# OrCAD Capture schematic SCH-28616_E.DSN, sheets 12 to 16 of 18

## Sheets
12 M-02 HDMI: size C
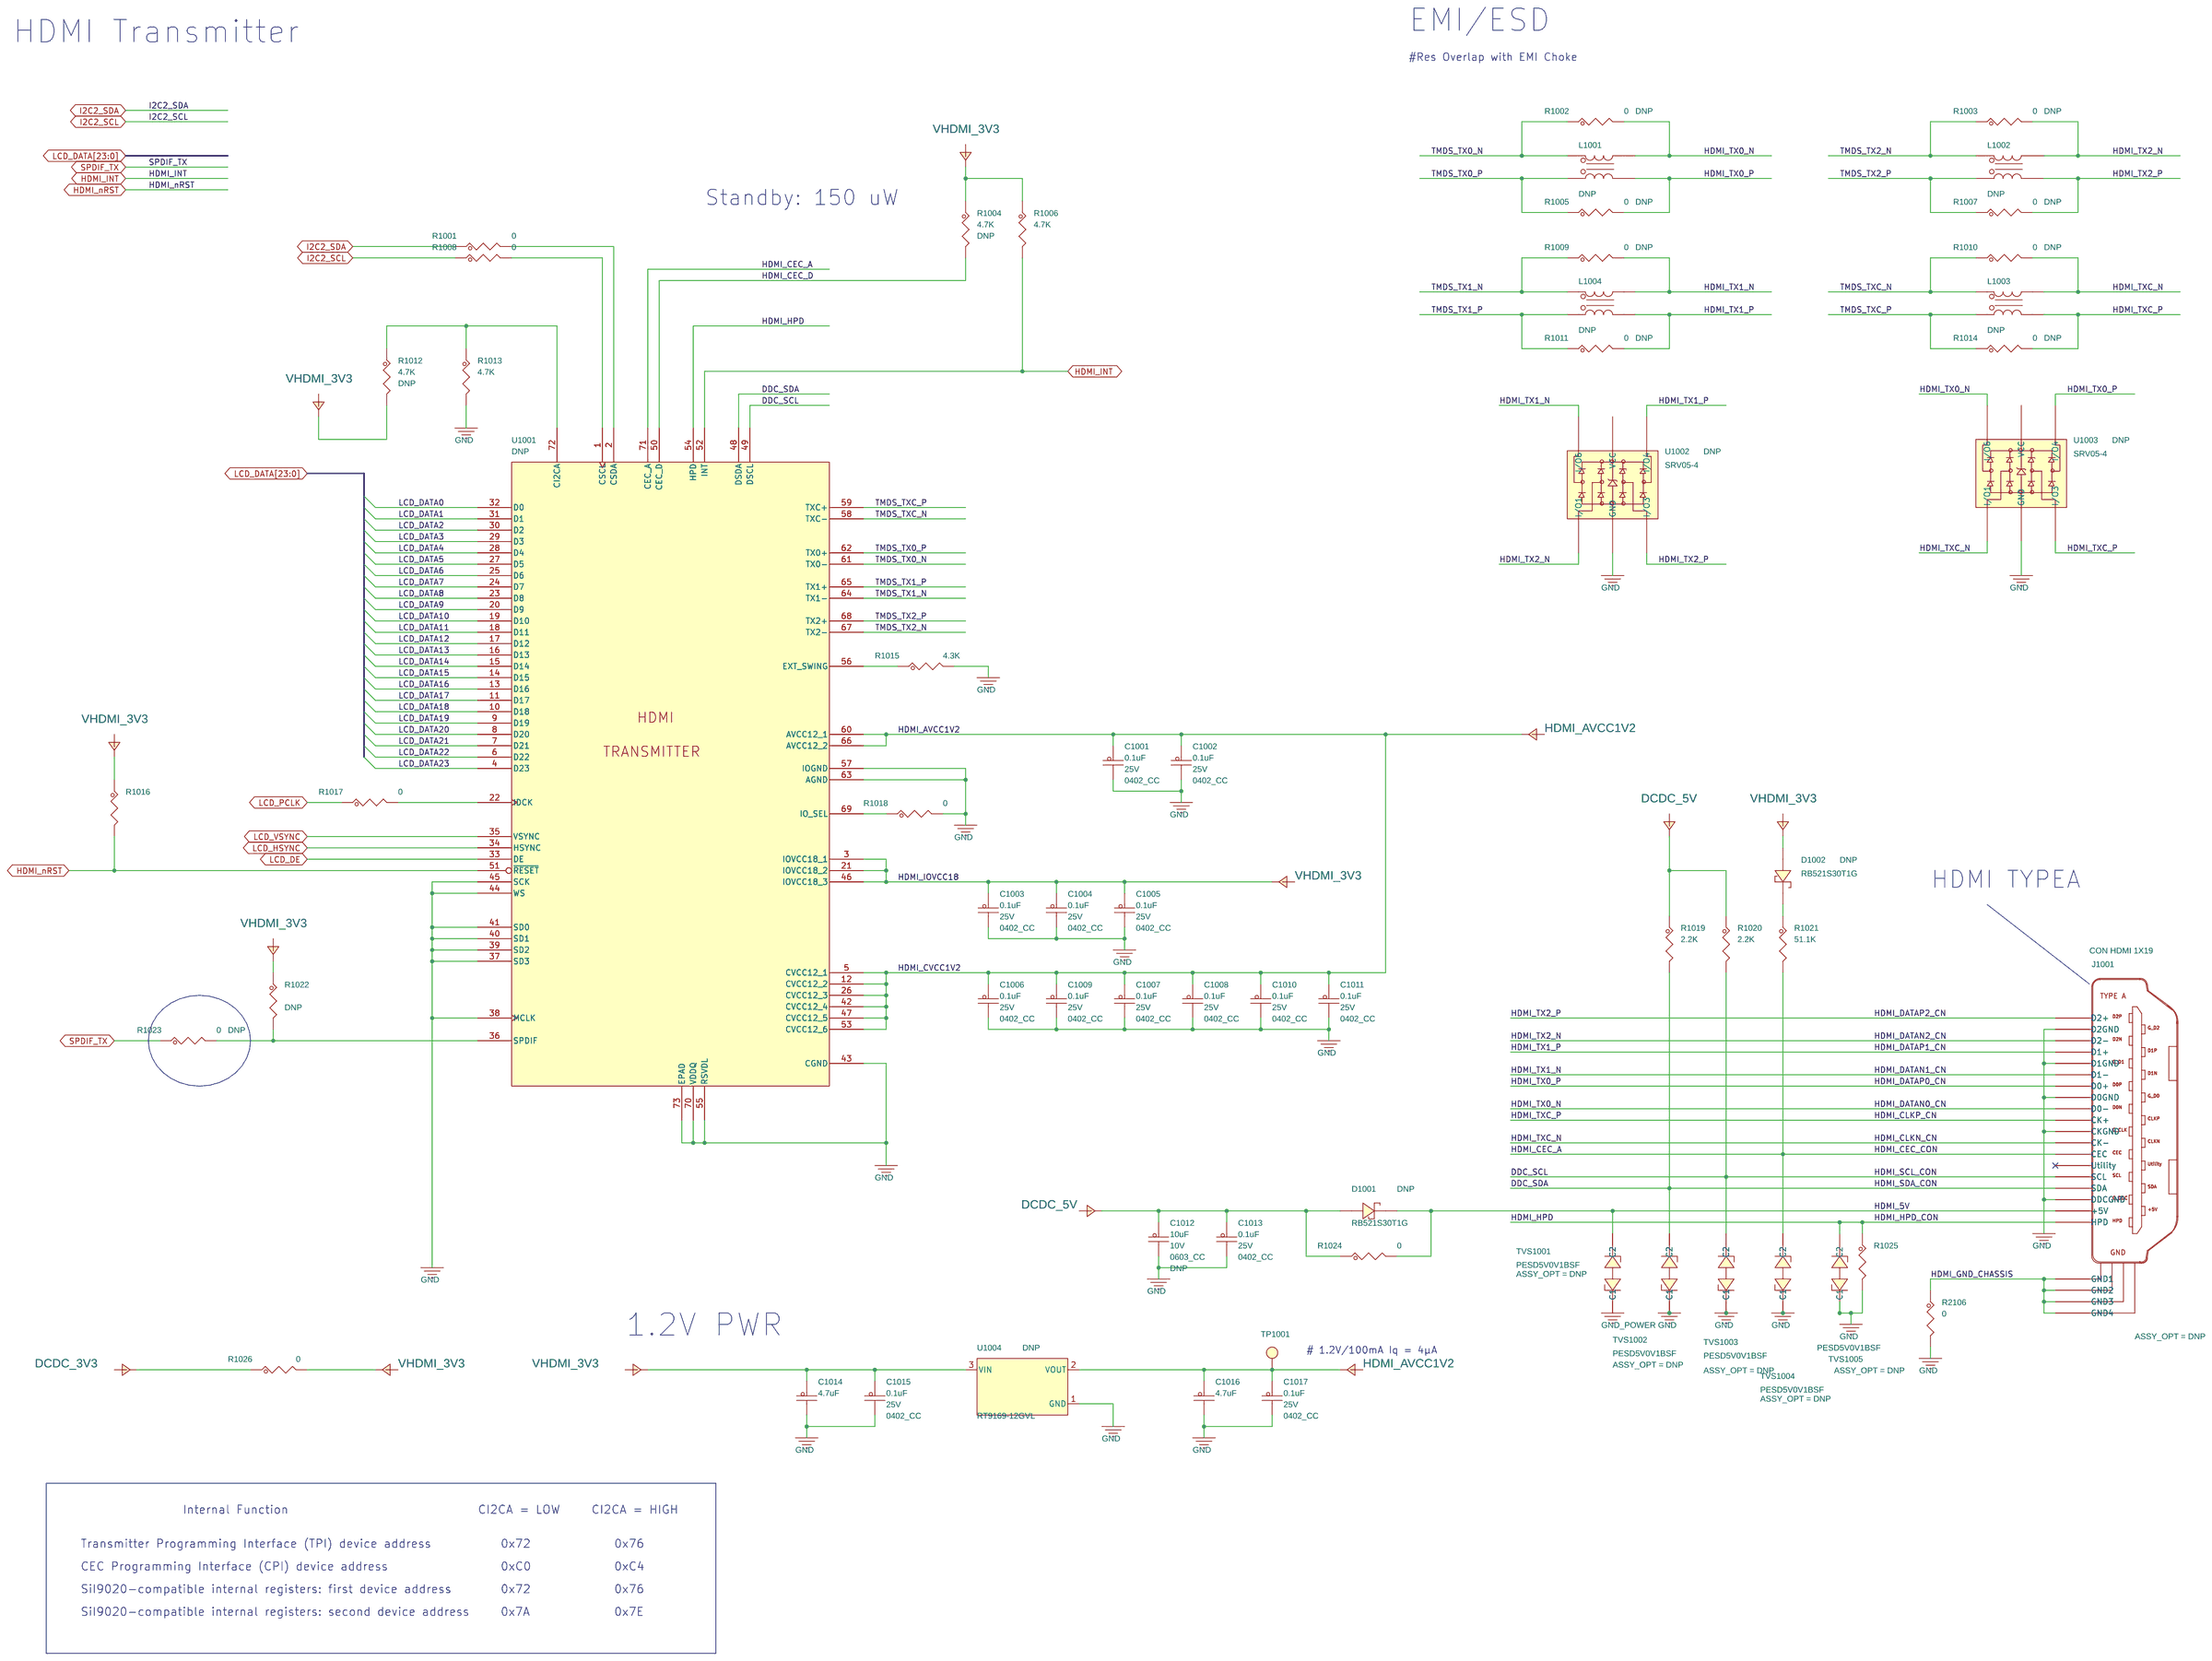
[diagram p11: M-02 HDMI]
13 M-07 Ethernet RMII x1: size C
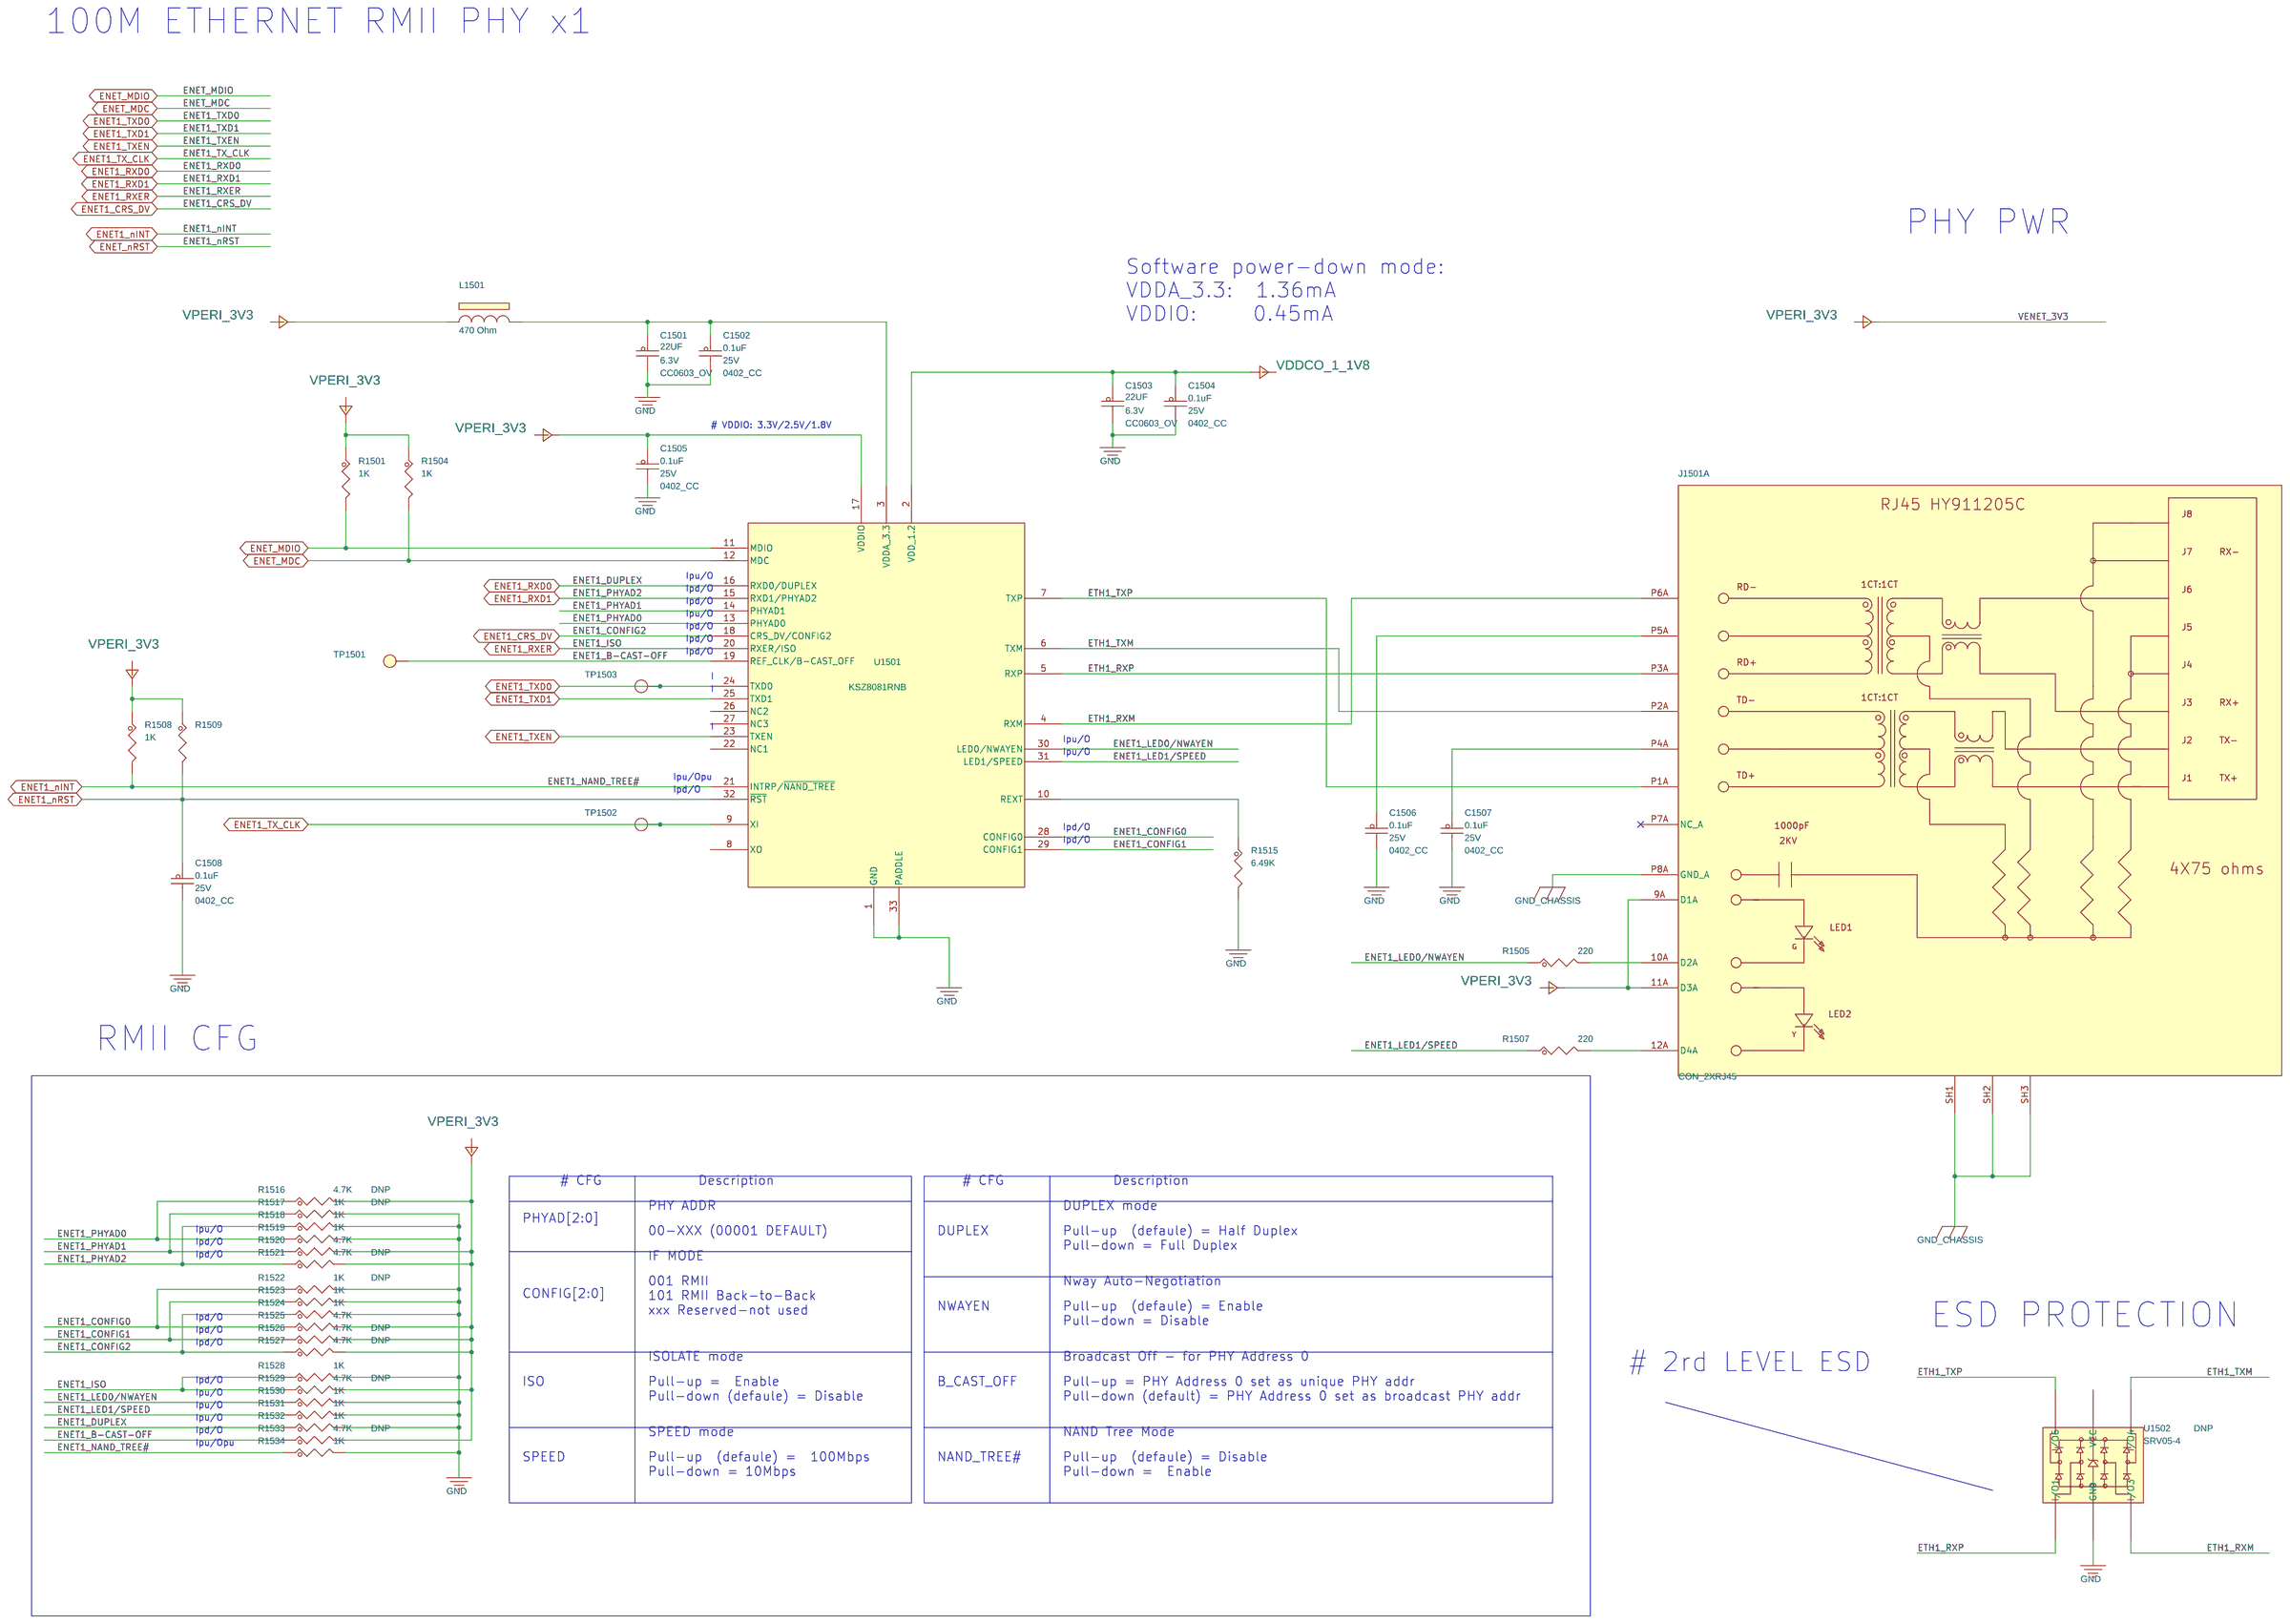
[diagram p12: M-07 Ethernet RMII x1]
14 M-08 Ethernet RMII x2: size C
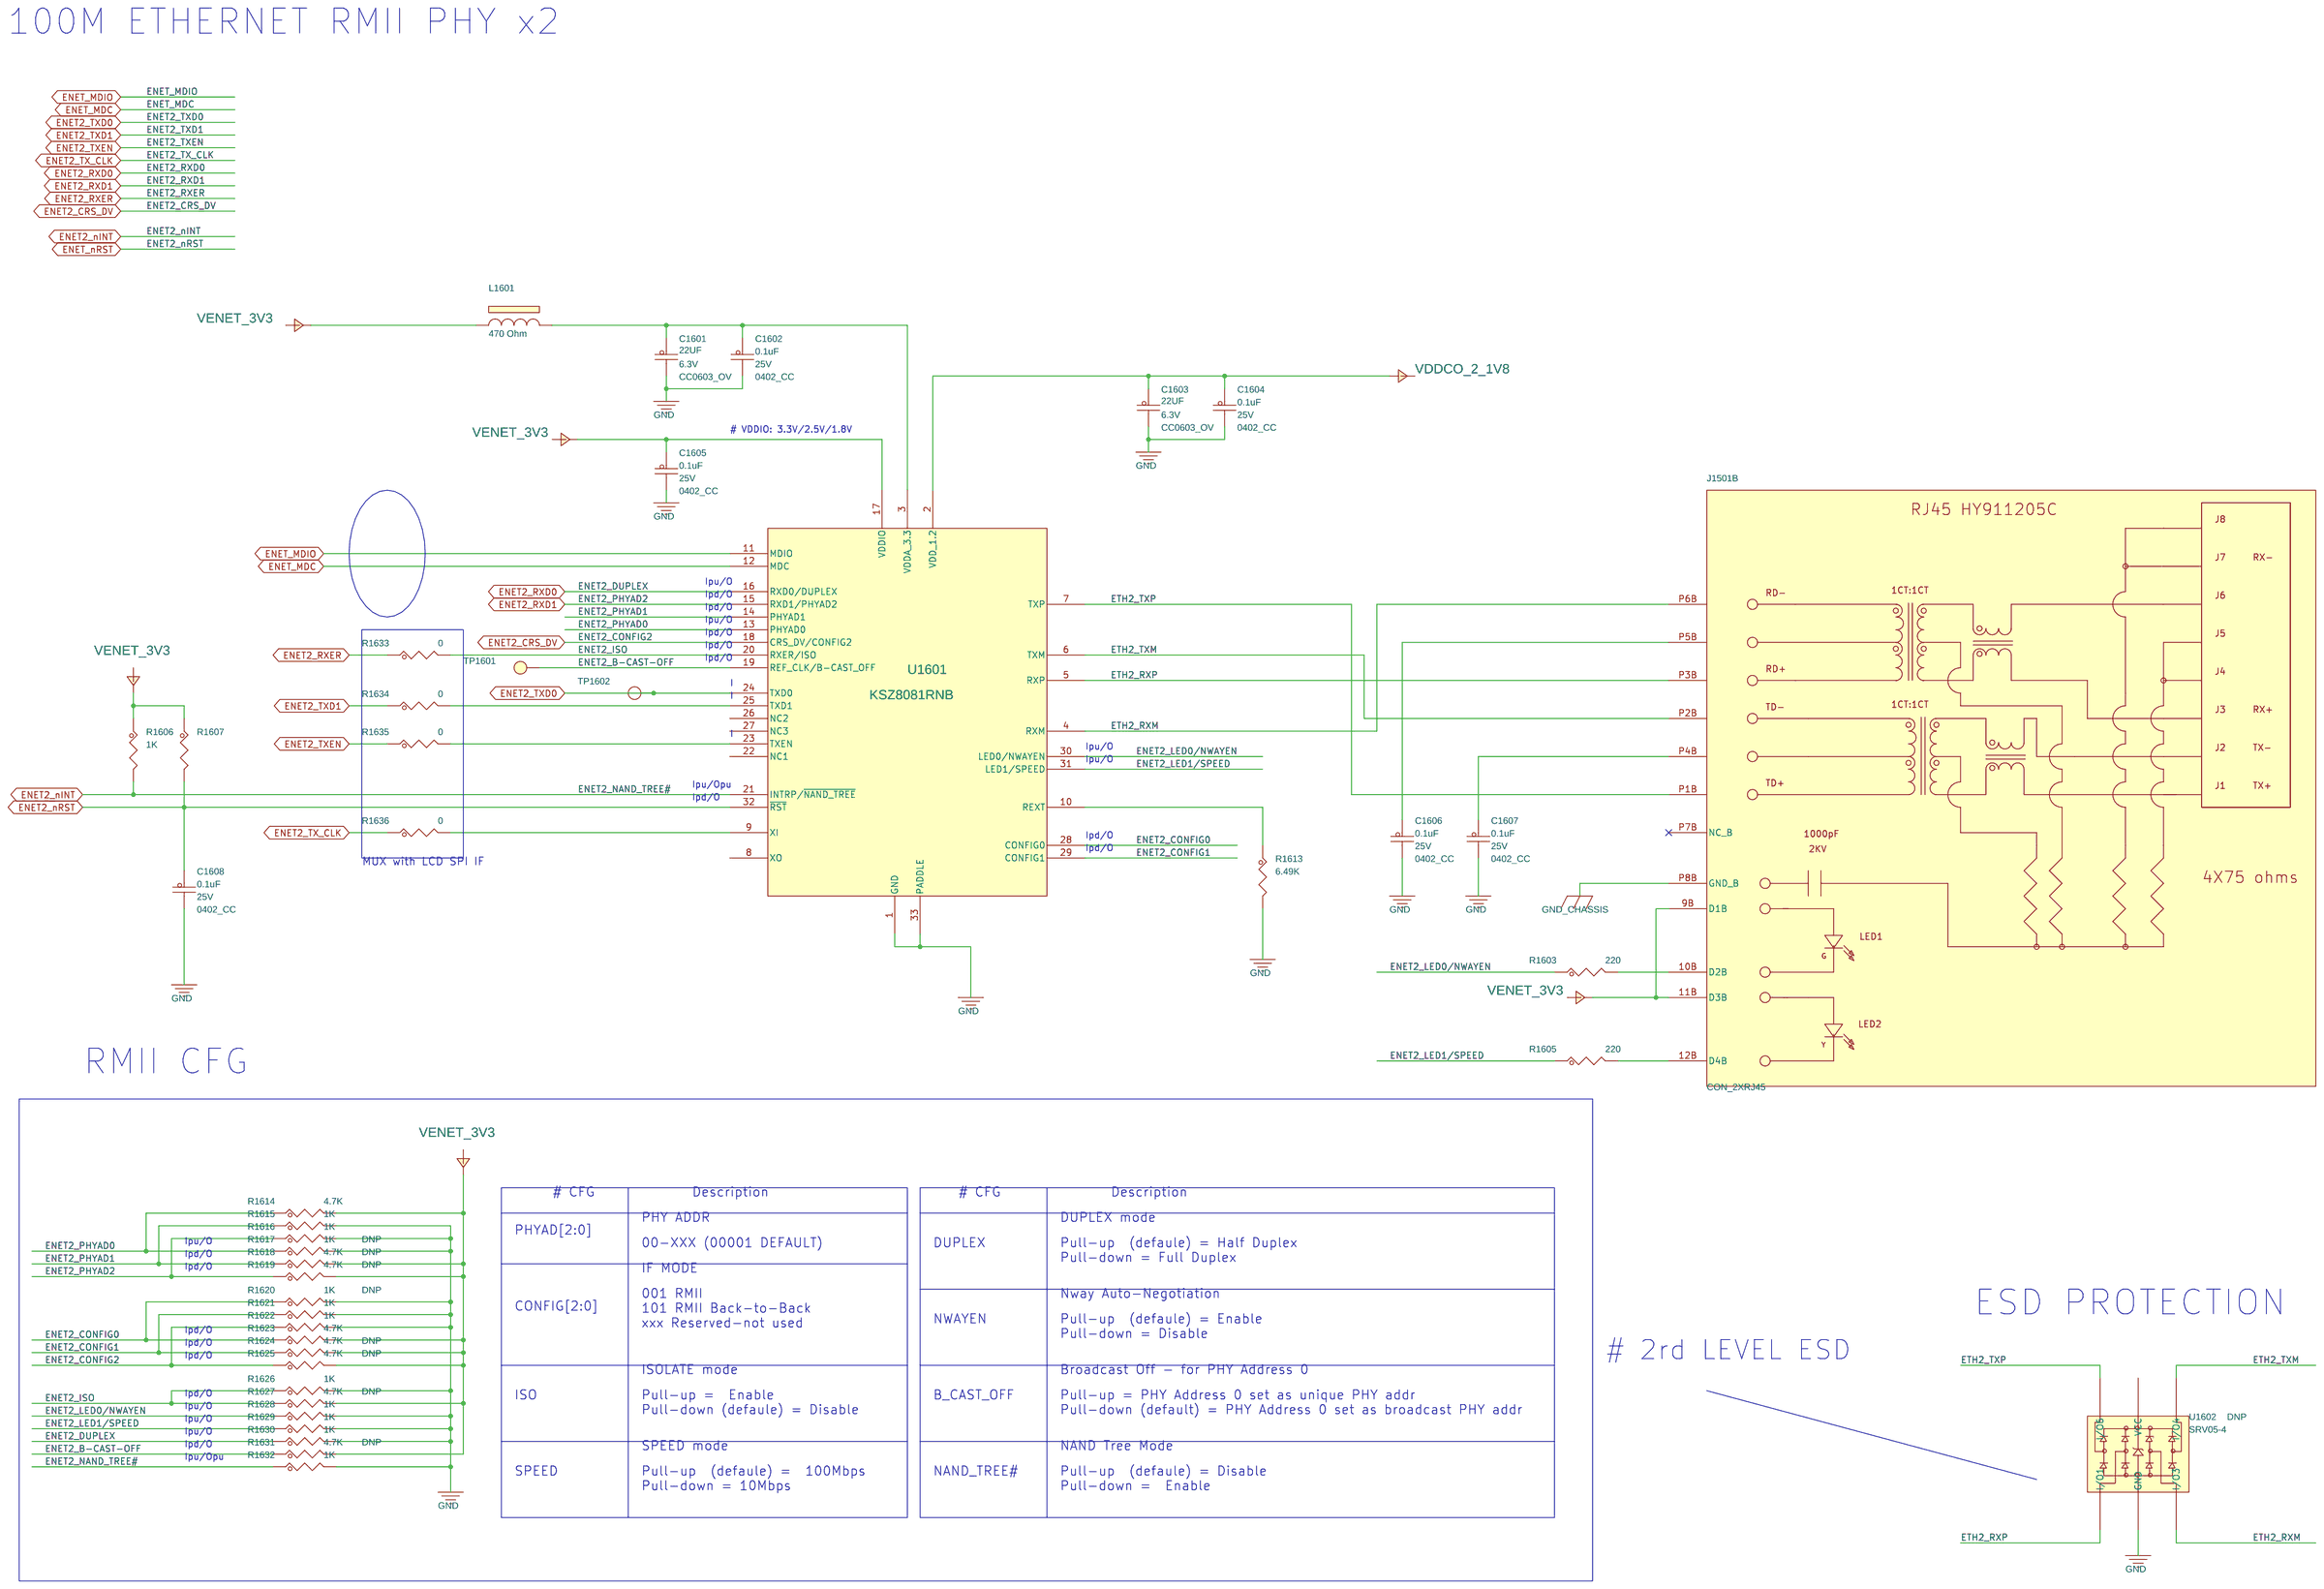
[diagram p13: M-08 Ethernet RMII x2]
15 M-13 SYS POWER: size C
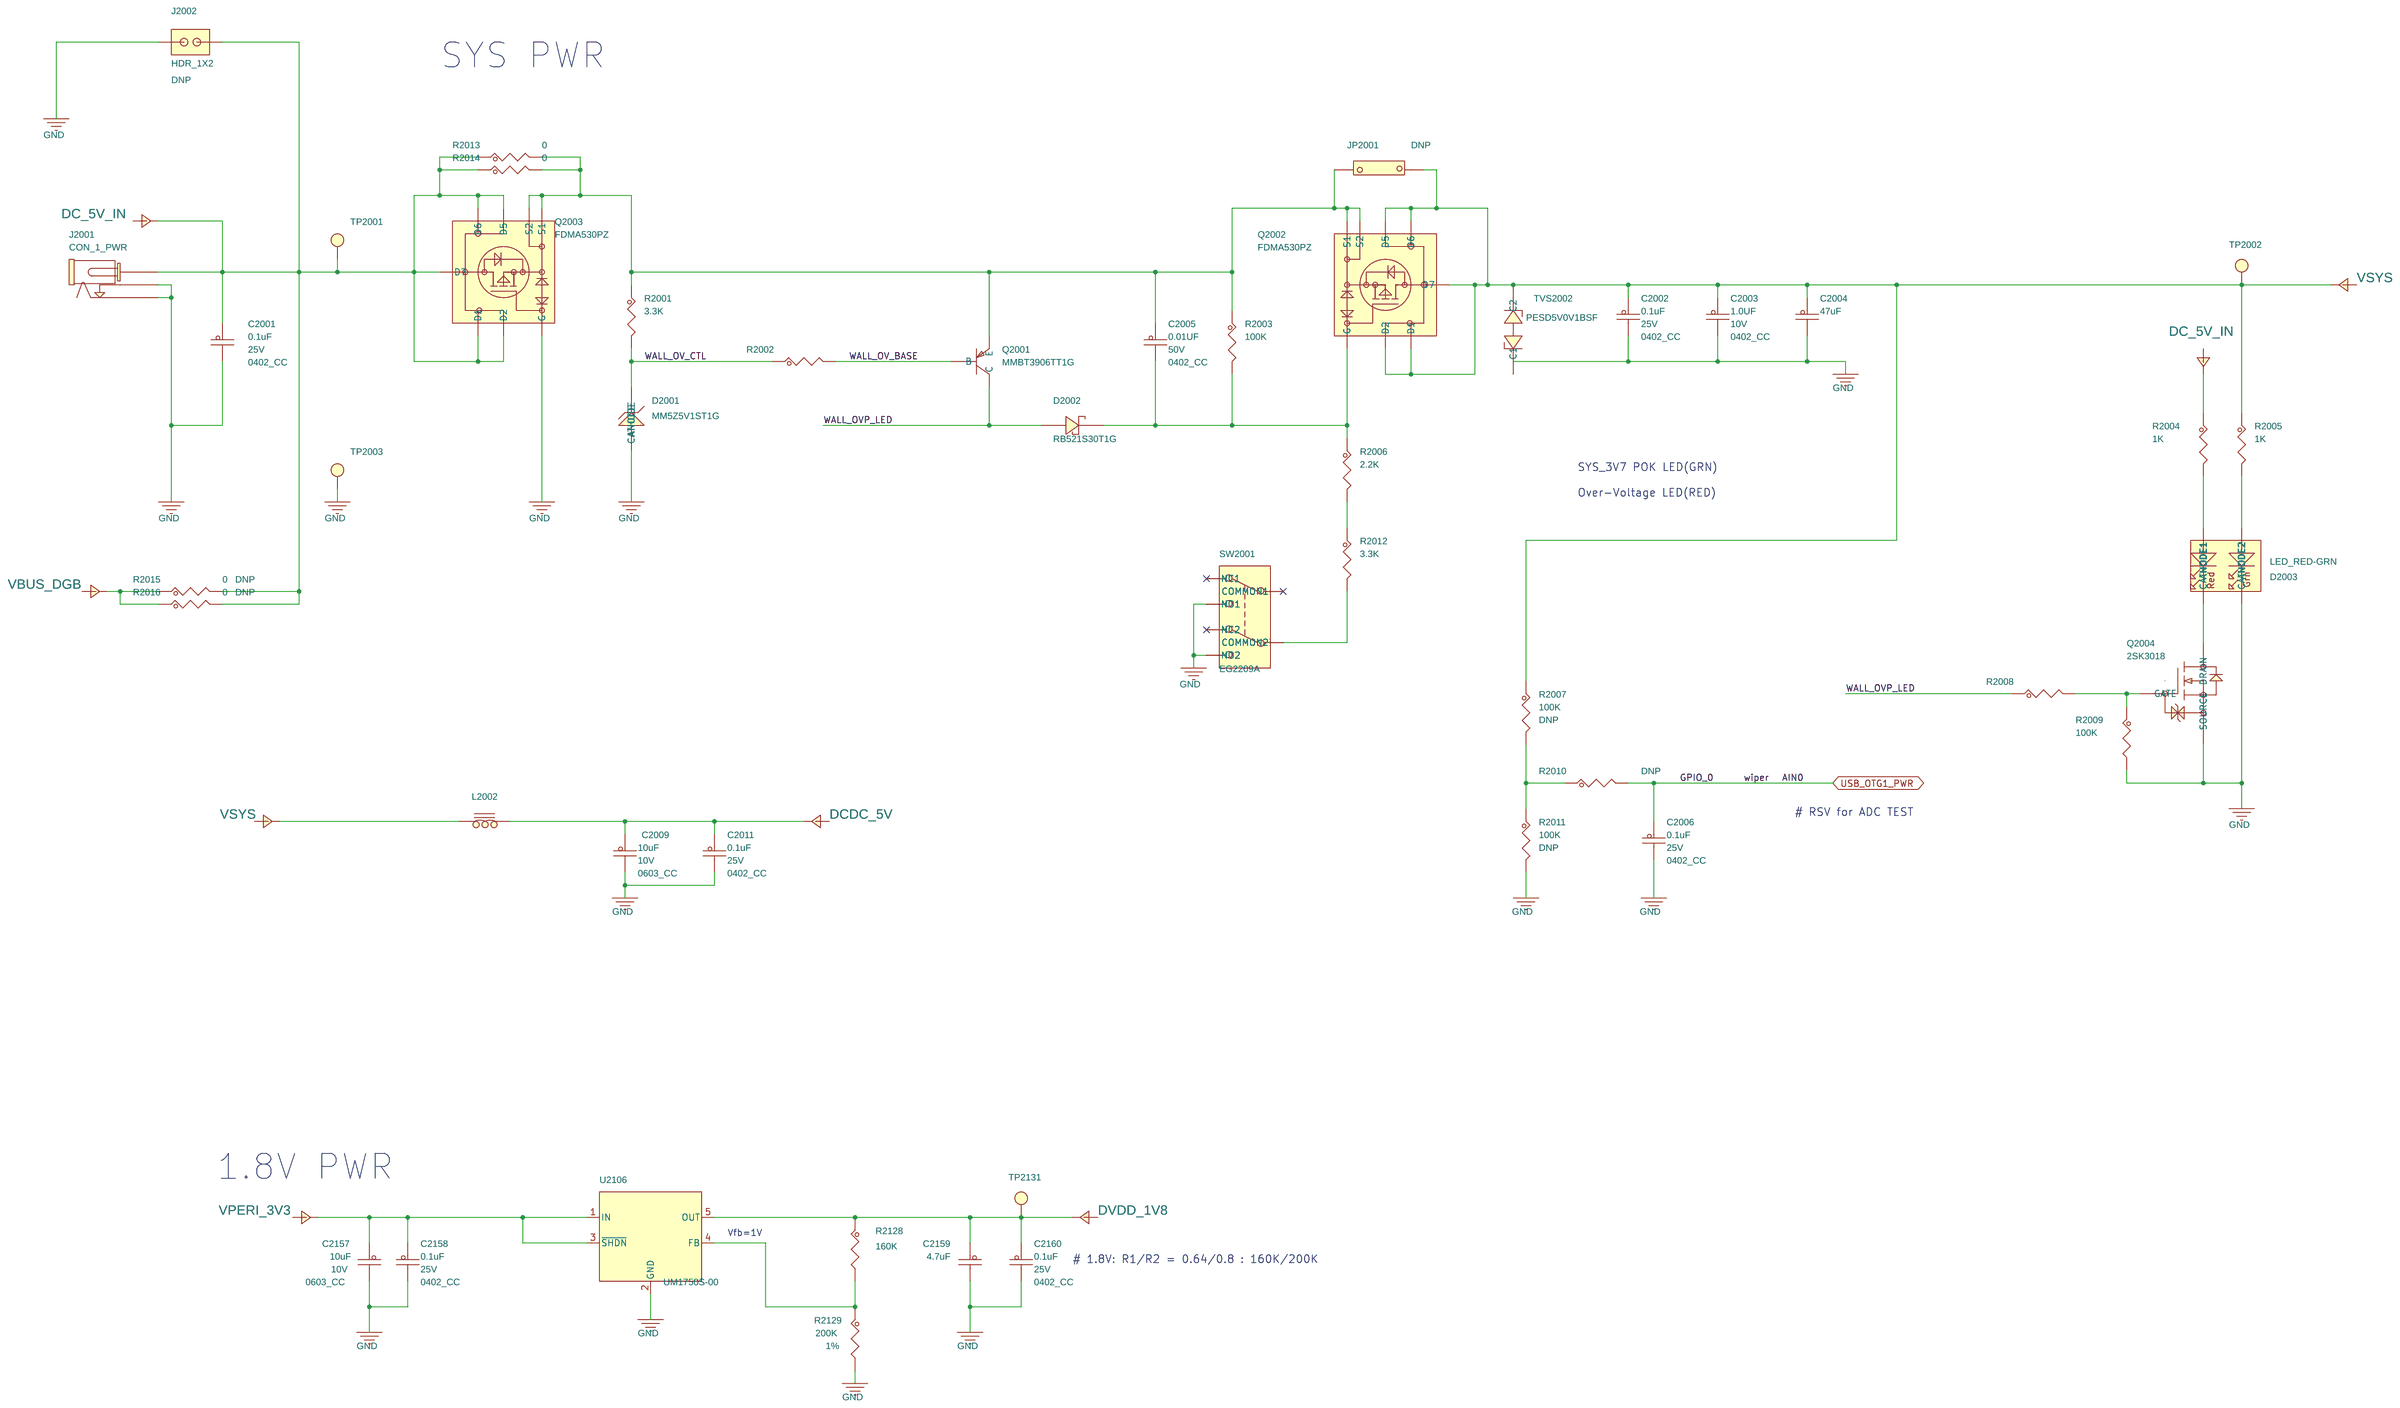
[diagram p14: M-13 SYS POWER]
16 M-12 Debug/JTAG: size C
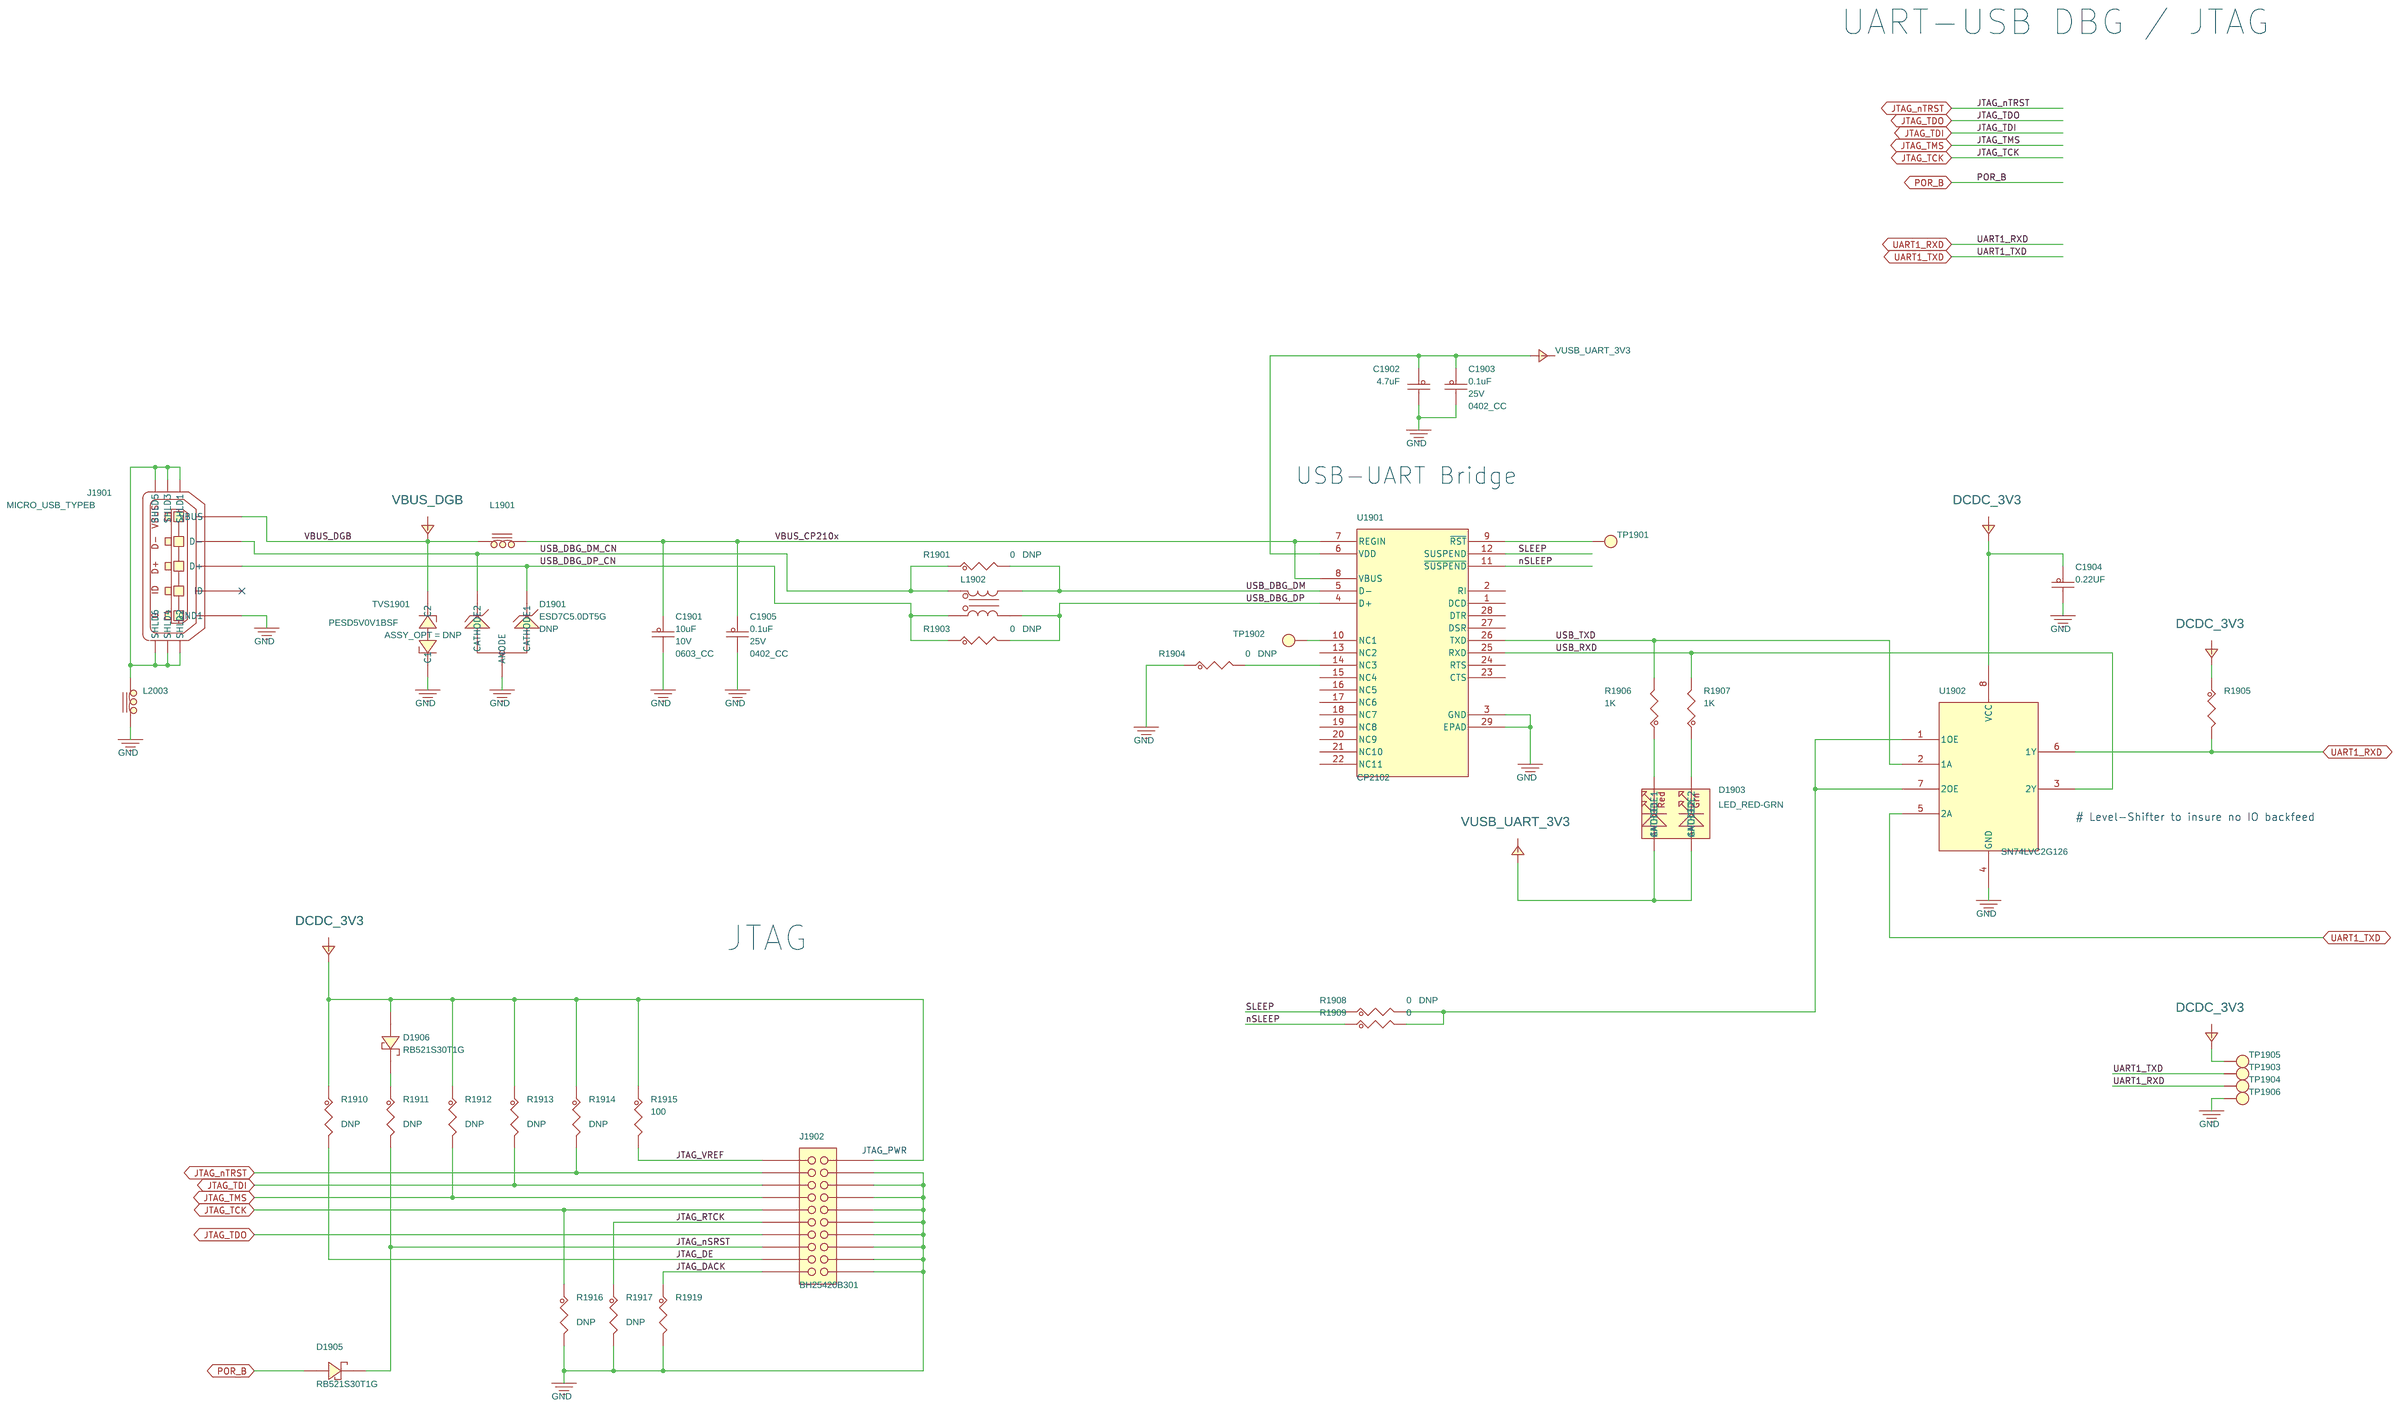
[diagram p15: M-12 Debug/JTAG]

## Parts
sheet M-02 HDMI
C1001  0.1uF  [0402_CC]
C1002  0.1uF  [0402_CC]
C1003  0.1uF  [0402_CC]
C1004  0.1uF  [0402_CC]
C1005  0.1uF  [0402_CC]
C1006  0.1uF  [0402_CC]
C1007  0.1uF  [0402_CC]
C1008  0.1uF  [0402_CC]
C1009  0.1uF  [0402_CC]
C1010  0.1uF  [0402_CC]
C1011  0.1uF  [0402_CC]
C1012  10uF  [0603_CC]
C1013  0.1uF  [0402_CC]
C1014  4.7uF  [cc0402_tol0p15]
C1015  0.1uF  [0402_CC]
C1016  4.7uF  [cc0402_tol0p15]
C1017  0.1uF  [0402_CC]
D1001  RB521S30T1G  [sod_523]
D1002  RB521S30T1G  [sod_523]
J1001  CON HDMI 1X19  [con_ra_hdmi_19p_0p5_sm_b]
L1001  90OHM  [ind4_choke_0805]
L1002  90OHM  [ind4_choke_0805]
L1003  90OHM  [ind4_choke_0805]
L1004  90OHM  [ind4_choke_0805]
R1001  0  [0402_CC]
R1002  0  [0402_CC]
R1003  0  [0402_CC]
R1004  4.7K  [0402_CC]
R1005  0  [0402_CC]
R1006  4.7K  [0402_CC]
R1007  0  [0402_CC]
R1008  0  [0402_CC]
R1009  0  [0402_CC]
R1010  0  [0402_CC]
R1011  0  [0402_CC]
R1012  4.7K  [0402_CC]
R1013  4.7K  [0402_CC]
R1014  0  [0402_CC]
R1015  4.3K  [0402_CC]
R1016  10K  [0402_CC]
R1017  0  [0402_CC]
R1018  0  [0402_CC]
R1019  2.2K  [0402_CC]
R1020  2.2K  [0402_CC]
R1021  51.1K  [0402_CC]
R1022  10K  [0402_CC]
R1023  0  [0402_CC]
R1024  0  [0402_CC]
R1025  10K  [0402_CC]
R1026  0  [0603_CC]
R2106  0  [0805_CC]
TP1001  TP_35MIL  [testpoint_35mil]
TVS1001  PESD5V0V1BSF  [dsn0603-2]
TVS1002  PESD5V0V1BSF  [dsn0603-2]
TVS1003  PESD5V0V1BSF  [dsn0603-2]
TVS1004  PESD5V0V1BSF  [dsn0603-2]
TVS1005  PESD5V0V1BSF  [dsn0603-2]
U1001  SiI9022A  [qfn72_0p5_10x10_4p85sq]
U1002  SRV05-4  [SOT23_S6]
U1003  SRV05-4  [SOT23_S6]
U1004  RT9169-12GVL  [sot23-3-1p95]
sheet M-07 Ethernet RMII x1
C1501  22UF  [CC0603_OV]
C1502  0.1uF  [0402_CC]
C1503  22UF  [CC0603_OV]
C1504  0.1uF  [0402_CC]
C1505  0.1uF  [0402_CC]
C1506  0.1uF  [0402_CC]
C1507  0.1uF  [0402_CC]
C1508  0.1uF  [0402_CC]
J1501  CON_2XRJ45  [CON_1X2_RJ45_1P27_TH_RA]  (sections A,B)
L1501  470 Ohm  [IND0603_CC]
R1501  1K  [0402_CC]
R1504  1K  [0402_CC]
R1505  220  [0402_CC]
R1507  220  [0402_CC]
R1508  1K  [0402_CC]
R1509  10K  [0402_CC]
R1515  6.49K  [0402_CC]
R1516  4.7K  [0402_CC]
R1517  1K  [0402_CC]
R1518  1K  [0402_CC]
R1519  1K  [0402_CC]
R1520  4.7K  [0402_CC]
R1521  4.7K  [0402_CC]
R1522  1K  [0402_CC]
R1523  1K  [0402_CC]
R1524  1K  [0402_CC]
R1525  4.7K  [0402_CC]
R1526  4.7K  [0402_CC]
R1527  4.7K  [0402_CC]
R1528  1K  [0402_CC]
R1529  4.7K  [0402_CC]
R1530  1K  [0402_CC]
R1531  1K  [0402_CC]
R1532  1K  [0402_CC]
R1533  4.7K  [0402_CC]
R1534  1K  [0402_CC]
TP1501  TP_35MIL  [testpoint_35mil]
TP1502  TPAD_015  [TPAD_015]
TP1503  TPAD_015  [TPAD_015]
U1501  KSZ8081RNB  [qfn32_0p5_ep3p3]
U1502  SRV05-4  [SOT23_S6]
sheet M-08 Ethernet RMII x2
C1601  22UF  [CC0603_OV]
C1602  0.1uF  [0402_CC]
C1603  22UF  [CC0603_OV]
C1604  0.1uF  [0402_CC]
C1605  0.1uF  [0402_CC]
C1606  0.1uF  [0402_CC]
C1607  0.1uF  [0402_CC]
C1608  0.1uF  [0402_CC]
L1601  470 Ohm  [IND0603_CC]
R1603  220  [0402_CC]
R1605  220  [0402_CC]
R1606  1K  [0402_CC]
R1607  10K  [0402_CC]
R1613  6.49K  [0402_CC]
R1614  4.7K  [0402_CC]
R1615  1K  [0402_CC]
R1616  1K  [0402_CC]
R1617  1K  [0402_CC]
R1618  4.7K  [0402_CC]
R1619  4.7K  [0402_CC]
R1620  1K  [0402_CC]
R1621  1K  [0402_CC]
R1622  1K  [0402_CC]
R1623  4.7K  [0402_CC]
R1624  4.7K  [0402_CC]
R1625  4.7K  [0402_CC]
R1626  1K  [0402_CC]
R1627  4.7K  [0402_CC]
R1628  1K  [0402_CC]
R1629  1K  [0402_CC]
R1630  1K  [0402_CC]
R1631  4.7K  [0402_CC]
R1632  1K  [0402_CC]
R1633  0  [0402_CC]
R1634  0  [0402_CC]
R1635  0  [0402_CC]
R1636  0  [0402_CC]
TP1601  TP_35MIL  [testpoint_35mil]
TP1602  TPAD_015  [TPAD_015]
U1601  KSZ8081RNB  [qfn32_0p5_ep3p3]
U1602  SRV05-4  [SOT23_S6]
sheet M-12 Debug/JTAG
C1901  10uF  [0603_CC]
C1902  4.7uF  [cc0402_tol0p15]
C1903  0.1uF  [0402_CC]
C1904  0.22UF  [CC0402_25]
C1905  0.1uF  [0402_CC]
D1901  ESD7C5.0DT5G  [sot-723]
D1903  LED_RED-GRN  [LED_DUAL_3025MM_SM]
D1905  RB521S30T1G  [sod_523]
D1906  RB521S30T1G  [sod_523]
J1901  MICRO_USB_TYPEB  [con_usb_type_b_sm]
J1902  BH25420B301  [hdr_2x10m_100_th]
L1901  120OHM  [0603_CC]
L1902  90OHM  [ind4_choke_0805]
L2003  120OHM  [0603_CC]
R1901  0  [0402_CC]
R1903  0  [0402_CC]
R1904  0  [0402_CC]
R1905  10K  [0402_CC]
R1906  1K  [0402_CC]
R1907  1K  [0402_CC]
R1908  0  [0402_CC]
R1909  0  [0402_CC]
R1910  10K  [0402_CC]
R1911  10K  [0402_CC]
R1912  10K  [0402_CC]
R1913  10K  [0402_CC]
R1914  10K  [0402_CC]
R1915  100  [0402_CC]
R1916  10K  [0402_CC]
R1917  10K  [0402_CC]
R1919  10K  [0402_CC]
TP1901  TP_35MIL  [testpoint_35mil]
TP1902  TP_35MIL  [testpoint_35mil]
TP1903  TP_35MIL  [testpoint_35mil]
TP1904  TP_35MIL  [testpoint_35mil]
TP1905  TP_35MIL  [testpoint_35mil]
TP1906  TP_35MIL  [testpoint_35mil]
TVS1901  PESD5V0V1BSF  [dsn0603-2]
U1901  CP2102  [qfn28_5x5mm_3p3_ep]
U1902  SN74LVC2G126  [SSOP8]
sheet M-13 SYS POWER
C2001  0.1uF  [0402_CC]
C2002  0.1uF  [0402_CC]
C2003  1.0UF  [0402_CC]
C2004  47uF  [0805_CC]
C2005  0.01UF  [0402_CC]
C2006  0.1uF  [0402_CC]
C2009  10uF  [0603_CC]
C2011  0.1uF  [0402_CC]
C2157  10uF  [0603_CC]
C2158  0.1uF  [0402_CC]
C2159  4.7uF  [cc0402_tol0p15]
C2160  0.1uF  [0402_CC]
D2001  MM5Z5V1ST1G  [sod_523_1p4]
D2002  RB521S30T1G  [sod_523]
D2003  LED_RED-GRN  [LED_DUAL_3025MM_SM]
J2001  CON_1_PWR  [con3_pwr_th]
J2002  HDR_1X2  [hdr102_100mil]
JP2001  SHORT_100mil  [100MIL_TH]
L2002  120OHM  [0603_CC]
Q2001  MMBT3906TT1G  [sc_75]
Q2002  FDMA530PZ  [MLP6_2X2MM_SLUG]
Q2003  FDMA530PZ  [MLP6_2X2MM_SLUG]
Q2004  2SK3018  [SOT323_3]
R2001  3.3K  [0603_CC]
R2002  10K  [0402_CC]
R2003  100K  [0402_CC]
R2004  1K  [0402_CC]
R2005  1K  [0402_CC]
R2006  2.2K  [0603_CC]
R2007  100K  [0402_CC]
R2008  10K  [0402_CC]
R2009  100K  [0402_CC]
R2010  1K  [0402_CC]
R2011  100K  [0402_CC]
R2012  3.3K  [0603_CC]
R2013  0  [0805_CC]
R2014  0  [0805_CC]
R2015  0  [0805_CC]
R2016  0  [0805_CC]
R2128  160K  [0402_CC]
R2129  200K  [0402_CC]
SW2001  EG2209A  [sw6_dpdt_11x6mm]
TP2001  TP_35MIL  [testpoint_35mil]
TP2002  TP_35MIL  [testpoint_35mil]
TP2003  TP_35MIL  [testpoint_35mil]
TP2131  TP_35MIL  [testpoint_35mil]
TVS2002  PESD5V0V1BSF  [dsn0603-2]
U2106  UM1750S-00  [sot23-5_a]

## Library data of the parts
C1001-C1011 C1013 C1015 C1017 C1502 C1504-C1508 C1602 C1604-C1608 C1903 C1905 C2002 C2011 C2158 C2160 = CAP_NP: CAP CER 0.1UF 25V 10% X5R 0402; AGILE_PN: 150-78633; CAD_APPROVED: Yes; FPLIST: CC0402_25,CC0402_HD,0402_CC; HEIGHT: 0.55MM; MFG_NAME01: YAGEO AMERICA; MFG_PN01: CC0402KRX5R8BB104; Package Size: 0402; ROHS: Yes; Rated Voltage: 25V; Temp Range: -55C to +85C; Tolerance: 10%; VOLTAGE: 25V
C1012 = CAP_NP: CAP CER 10UF 10V 20% X5R 0603; AGILE_PN: 150-78609; ASSY_OPT: DNP; CAD_APPROVED: Yes; FPLIST: CC0603_OV,CC0603,0603_CC; HEIGHT: 1.016MM; MFG_NAME01: TAIYO YUDEN; MFG_PN01: LMK107BJ106MALTD; Package Size: 0603; Package Type: Paper Tape; ROHS: Yes; Rated Voltage: 10V; Temp Range: -55C to +85C; Tolerance: 20%; VOLTAGE: 10V
C1014 C1016 C1902 C2159 = CAP_NP: CAP CER 4.7UF 6.3V 20% X5R 0402; AGILE_PN: 150-78463; CAD_APPROVED: Yes; FPLIST: CC0402_25,CC0402_HD,0402_CC; HEIGHT: 0.65MM; MFG_NAME01: TDK; MFG_PN01: C1005X5R0J475M; ROHS: Yes; Rated Voltage: 6.3V; Temp Range: -55C to +85C; Tolerance: 20%; VOLTAGE: 6.3V; voltage rating: 6.3V
D1001 D1002 = DIODE_SCHTKY: DIODE SCH 200MA 30V AEC-Q101 SOD-523; 3D_Mechanical_Footprint_File: http://fcl.am.freescale.net/ALLEGRO/step/sod_523.STEP; AGILE_PN: 480-78501; ASSY_OPT: DNP; CAD_APPROVED: Yes; HEIGHT: 0.7MM; MFG_NAME01: ON SEMICONDUCTOR; ROHS: Yes; Rated Voltage: 30V
J1001 = ATOM010130010052_HDMI_19P: CON 1X19 HDMI SMT 0.5MM 249H AU; 3D_Mechanical_Footprint_File: http://fcl.am.freescale.net/ALLEGRO/step/con_ra_hdmi_19p_0p5_sm_b.STEP; AGILE_PN: 211-80845; ASSY_OPT: DNP; CAD_APPROVED: Yes; HEIGHT: 6.33MM; MFG_NAME01: SHENZHEN ATOM TECHNOLOGY CO.,LTD; MFG_PN01: HD119F-3A04205; Package Size: 15X12.05X6.13MM; Package Type: SMT; ROHS: Yes; Temp Range: -20°C to +85°C
L1001-L1004 = DLW43: IND CHK 90 OHM@100MHZ 330MA 25% 0805; 3D_Mechanical_Footprint_File: http://fcl.am.freescale.net/ALLEGRO/step/ind4_choke_0805_39h.STEP; AGILE_PN: 180-76336; ASSY_OPT: DNP; CAD_APPROVED: Yes; HEIGHT: 1MM; MFG_NAME01: MURATA; MFG_PN01: DLW21HN900SQ2L; PART_TYPE: CHOKE; ROHS: Yes; Temp Range: -40°C to +85°C; Tolerance: 25%
R1001 R1008 R1017 R1018 R1024 R1633-R1636 R1909 = RES: RES MF ZERO OHM 1/16W 5% 0402; AGILE_PN: 470-75394; CAD_APPROVED: Yes; FPLIST: RC0402_25,RC0402_HD,RC0402_X2,0402_CC; HEIGHT: 0.45 MM; MFG_NAME01: YAGEO AMERICA; MFG_PN01: RC0402JR-070RL; ROHS: Yes; Tolerance: 5%
R1002 R1003 R1005 R1007 R1009-R1011 R1014 R1023 R1901 R1903 R1904 R1908 = RES: RES MF ZERO OHM 1/16W 5% 0402; AGILE_PN: 470-75394; ASSY_OPT: DNP; CAD_APPROVED: Yes; FPLIST: RC0402_25,RC0402_HD,RC0402_X2,0402_CC; HEIGHT: 0.45 MM; MFG_NAME01: YAGEO AMERICA; MFG_PN01: RC0402JR-070RL; ROHS: Yes; Tolerance: 5%
R1004 R1012 R1516 R1521 R1526 R1527 R1533 R1618 R1619 R1624 R1625 R1627 R1631 = RES: RES MF 4.7K 1/16W 5% 0402; AGILE_PN: 470-75626; ASSY_OPT: DNP; CAD_APPROVED: Yes; FPLIST: RC0402_25,RC0402_HD,0402_CC; HEIGHT: 0.41mm; MFG_NAME01: NIC COMPONENTS CORP; MFG_PN01: NRCL04J472TRF; ROHS: Yes; Tolerance: 5%
R1006 R1013 R1520 R1525 R1529 R1614 R1623 = RES: RES MF 4.7K 1/16W 5% 0402; AGILE_PN: 470-75626; CAD_APPROVED: Yes; FPLIST: RC0402_25,RC0402_HD,0402_CC; HEIGHT: 0.41mm; MFG_NAME01: NIC COMPONENTS CORP; MFG_PN01: NRCL04J472TRF; ROHS: Yes; Tolerance: 5%
R1015 = RES: RES MF 4.3K 1/10W 1% AEC-Q200 0402; AGILE_PN: 470-30905; CAD_APPROVED: Yes; FPLIST: RC0402_25,RC0402_HD,0402_CC; HEIGHT: 0.40 MM; MFG_NAME01: KOA SPEER; MFG_PN01: RK73H1ETTP4301F; ROHS: Yes; Temp Range: -55°C to +155°C; Temp_Range: -55°C to +155°C; Tolerance: 1%
R1016 R1025 R1509 R1607 R1905 R1919 R2008 = RES: RES MF 10K 1/16W 5% 0402; AGILE_PN: 470-75557; CAD_APPROVED: Yes; FPLIST: RC0402_25,RC0402_HD,0402_CC; HEIGHT: 0.4 MM; MFG_NAME01: VISHAY INTERTECHNOLOGY; MFG_PN01: CRCW040210K0JNED; ROHS: Yes; Tolerance: 5%
R1019 R1020 = RES: RES MF 2.2K 1/16W 5% 0402; AGILE_PN: 470-75636; CAD_APPROVED: Yes; FPLIST: RC0402_25,RC0402_HD,0402_CC; HEIGHT: 0.4 MM; MFG_NAME01: BOURNS; MFG_PN01: CR0402-JW-222GLF; ROHS: Yes; Tolerance: 5%
R1021 = RES: RES MF 51.1K  1/16W 1% 0402; AGILE_PN: 470-31028; CAD_APPROVED: Yes; FPLIST: RC0402_25,RC0402_HD,0402_CC; HEIGHT: 0.40 MM; MFG_NAME01: YAGEO AMERICA; MFG_PN01: RT0402FRE0751K1L; ROHS: Yes; Tolerance: 1%
R1022 R1910-R1914 R1916 R1917 = RES: RES MF 10K 1/16W 5% 0402; AGILE_PN: 470-75557; ASSY_OPT: DNP; CAD_APPROVED: Yes; FPLIST: RC0402_25,RC0402_HD,0402_CC; HEIGHT: 0.4 MM; MFG_NAME01: VISHAY INTERTECHNOLOGY; MFG_PN01: CRCW040210K0JNED; ROHS: Yes; Tolerance: 5%
R1026 = RES: RES MF ZERO OHM 1/10W -- 0603; AGILE_PN: 470-80866; CAD_APPROVED: Yes; FPLIST: RC0603_OV,RC0603,R603-X2,0603_CC; HEIGHT: 0.6MM; MFG_NAME01: YAGEO AMERICA; MFG_PN01: RC0603FR-070RL; ROHS: Yes; Temp Range: –55 °C to +155 °C
R2013 R2014 R2106 = RES: RES MF ZERO OHM 1/8W -- 0805; AGILE_PN: 470-75442; CAD_APPROVED: Yes; FPLIST: RC0805_OV,RC0805,RC0805_OV_3P,0805_CC; HEIGHT: 0.7 MM; MFG_NAME01: YAGEO AMERICA; MFG_PN01: RC0805JR-070RL; ROHS: Yes; Temp Range: –55 °C to +155 °C; Tolerance: 5%
TP1001 TP1501 TP1601 TP1901-TP1906 TP2001-TP2003 TP2131 = T_POINT_R: TEST POINT PAD .035 SMT, no part to order; AGILE_PN: 510-75618; CAD_APPROVED: Yes; HEIGHT: 0.1MM; ROHS: Yes
TVS1001-TVS1005 TVS1901 = DIODE_BIDIR: DIODE BIDIR ESD PROT 3.5pF 5V 1A SOD-962; 3D_Mechanical_Footprint_File: http://fcl.am.freescale.net/ALLEGRO/step/dsn0603-2.STEP; AGILE_PN: 480-79836; ASSY_OPT: DNP; CAD_APPROVED: Yes; HEIGHT: 0.32MM; MFG_NAME01: NEXPERIA; MFG_PN01: PESD5V0V1BSF,315; Temp Range: -55°C to +150°C
U1001 = SiI9022A: IC XMTR HDMI 165MHZ 1.8/3.3V QFN72; 3D_Mechanical_Footprint_File: http://fcl.am.freescale.net/ALLEGRO/step/qfn72_0p5_10x10_4p85sq.STEP; AGILE_PN: 312-79886; ASSY_OPT: DNP; CAD_APPROVED: Yes; HEIGHT: 0.9MM; MFG_NAME01: LATTICE SEMICONDUCTOR CORPORATION; MFG_PN01: SiI9022ACNU; ROHS: Yes; Temp Range: -20°C to +85°C
U1002 U1003 U1502 U1602 = SRV05-4: DIODE TVS ARRAY 12A 5V 300W SOT23_S6; 3D_Mechanical_Footprint_File: http://fcl.am.freescale.net/ALLEGRO/step/SOT23_S6.STEP; AGILE_PN: 480-75205; ASSY_OPT: DNP; CAD_APPROVED: Yes; HEIGHT: 1.45mm; MFG_NAME01: SEMTECH CORP; MFG_PN01: SRV05-4.TCT; ROHS: Yes; Rated Voltage: 5V
U1004 = RT9169_3P: IC VREG LDO 1.2V 100mA 2-6V SOT23-3; AGILE_PN: 315-80512; ASSY_OPT: DNP; CAD_APPROVED: Yes; HEIGHT: 1.295 MM; MFG_NAME01: RICHTEK; ROHS: Yes; VOLTAGE: 1.2V
C1501 C1503 C1601 C1603 = CAP_NP: CAP CER 22UF 6.3V 20% X5R 0603; AGILE_PN: 150-78467; CAD_APPROVED: Yes; FPLIST: CC0603_OV,CC0603,0603_CC; HEIGHT: 1MM; MFG_NAME01: SAMSUNG; MFG_PN01: CL10A226MQ8NRNE; Package Size: 0603; ROHS: Yes; Rated Voltage: 6.3V; Temp Range: -55C to +85C; Tolerance: 20%; VOLTAGE: 6.3V; voltage rating: 6.3V
J1501 = RJ45_MAG_LED_24P: CON RJ45 DUAL SHLD RA TH 50MIL SP 609H AU 120L; AGILE_PN: 210-80770; CAD_APPROVED: Yes; HEIGHT: 15.46 MM; MFG_NAME01: HANRUN ELECTRONICS CO., LTD; MFG_PN01: HY911205C; Package Type: THD; ROHS: Yes
L1501 L1601 = INDUCTOR_FERRITE: IND FER BEAD 470 OHM@100MHZ 1A 25% 0603; AGILE_PN: 180-77776; CAD_APPROVED: Yes; FPLIST: IND_0603,IND0603_CC; HEIGHT: 0.95MM; MFG_NAME01: murata; MFG_PN01: BLM18PG471SN1D; PART_TYPE: FERRITE\BEAD; ROHS: Yes; Tolerance: 25%
R1501 R1504 R1508 R1518 R1519 R1523 R1524 R1530-R1532 R1534 R1606 R1615 R1616 R1621 R1622 R1626 R1628-R1630 R1632 R1906 R1907 R2004 R2005 = RES: RES MF 1.0K 1/16W 5% 0402; AGILE_PN: 470-75555; CAD_APPROVED: Yes; FPLIST: RC0402_25,RC0402_HD,RC0402_X2,0402_CC; HEIGHT: 0.41mm; MFG_NAME01: VISHAY INTERTECHNOLOGY; MFG_PN01: CRCW04021K00JNED; ROHS: Yes; Tolerance: 5%
R1505 R1507 R1603 R1605 = RES: RES MF 220 OHM 1/16W 5% 0402; AGILE_PN: 470-75607; CAD_APPROVED: Yes; FPLIST: RC0402_25,RC0402_HD,0402_CC; HEIGHT: 0.45mm; MFG_NAME01: VENKEL COMPANY; MFG_PN01: CR0402-16W-221JT; ROHS: Yes; Tolerance: 5%
R1515 R1613 = RES: RES MF 6.49K  1/16W 1% 0402; AGILE_PN: 470-30927; CAD_APPROVED: Yes; FPLIST: RC0402_25,RC0402_HD,0402_CC; HEIGHT: 0.40 MM; MFG_NAME01: WALSIN TECHNOLOGY CORP.; MFG_PN01: WR04X6491FTL; ROHS: Yes; Tolerance: 1%
R1517 R1522 R1528 R1617 R1620 R2010 = RES: RES MF 1.0K 1/16W 5% 0402; AGILE_PN: 470-75555; ASSY_OPT: DNP; CAD_APPROVED: Yes; FPLIST: RC0402_25,RC0402_HD,RC0402_X2,0402_CC; HEIGHT: 0.41mm; MFG_NAME01: VISHAY INTERTECHNOLOGY; MFG_PN01: CRCW04021K00JNED; ROHS: Yes; Tolerance: 5%
TP1502 TP1503 TP1602 = TESTLOOP: TEST POINT PAD 15MIL DIA SMT, NO PART TO ORDER; AGILE_PN: 211-76645; CAD_APPROVED: Yes; HEIGHT: 0.1MM; MFG_NAME01: NOTACOMPONENT; MFG_PN01: NOTACOMPONENT; ROHS: Yes
U1501 U1601 = KSZ8081RNB_32P: IC XCVR 10/100M EPHY 3.3V QFN32; 3D_Mechanical_Footprint_File: http://fcl.am.freescale.net/ALLEGRO/step/qfn32_0p5_ep3p3.STEP; AGILE_PN: 312-81089; CAD_APPROVED: Yes; HEIGHT: 0.9MM; MFG_NAME01: MICREL; MFG_PN01: KSZ8081RNBIA; ROHS: Yes; VOLTAGE: 3-3.6V
C1901 C2009 C2157 = CAP_NP: CAP CER 10UF 10V 20% X5R 0603; AGILE_PN: 150-78609; CAD_APPROVED: Yes; FPLIST: CC0603_OV,CC0603,0603_CC; HEIGHT: 1.016MM; MFG_NAME01: TAIYO YUDEN; MFG_PN01: LMK107BJ106MALTD; Package Size: 0603; Package Type: Paper Tape; ROHS: Yes; Rated Voltage: 10V; Temp Range: -55C to +85C; Tolerance: 20%; VOLTAGE: 10V
C1904 = CAP_NP: CAP CER 0.22UF 10V 10% X5R 0402; AGILE_PN: 150-77358; CAD_APPROVED: Yes; FPLIST: CC0402_25,CC0402_HD,0402_CC; HEIGHT: 0.55MM; MFG_NAME01: NIC COMPONENTS CORP; MFG_PN01: NMC0402X5R224K10TRPF; ROHS: Yes; Rated Voltage: 10V; Temp Range: -55C to +85C; Tolerance: 10%; VOLTAGE: 10V
D1901 = DZ_DUAL_CK_C1C2A: DIODE TVS 1A 5.0V AEC-Q101 SOT-723; 3D_Mechanical_Footprint_File: http://fcl.am.freescale.net/ALLEGRO/step/sot-723.STEP; AGILE_PN: 480-78836; ASSY_OPT: DNP; CAD_APPROVED: Yes; HEIGHT: 0.55MM; MFG_NAME01: ON SEMICONDUCTOR; ROHS: Yes; Rated Voltage: 5V
D1903 = LED_DUAL_SEP_RG: LED RED GRN DUAL 30/25MA SMT; 3D_Mechanical_Footprint_File: http://fcl.am.freescale.net/ALLEGRO/step/led_dual_3025mm_sm.STEP; AGILE_PN: 370-75097; CAD_APPROVED: Yes; HEIGHT: 1.1MM; MFG_NAME01: KINGBRIGHT; MFG_PN01: APB3025ESGC-F01
D1905 D1906 D2002 = DIODE_SCHTKY: DIODE SCH 200MA 30V AEC-Q101 SOD-523; 3D_Mechanical_Footprint_File: http://fcl.am.freescale.net/ALLEGRO/step/sod_523.STEP; AGILE_PN: 480-78501; CAD_APPROVED: Yes; HEIGHT: 0.7MM; MFG_NAME01: ON SEMICONDUCTOR; ROHS: Yes; Rated Voltage: 30V
J1901 = USB_MICRO_B_SKT: CON 1X5 MICROUSB_TYPE_B_FEMALE RA SHLD SMT 0.65MM SP 110H AU; AGILE_PN: 211-79712; CAD_APPROVED: Yes; HEIGHT: 2.795MM; MFG_NAME01: SHENZHEN ATOM TECHNOLOGY CO.,LTD; MFG_PN01: USB205FB-C1013203; ROHS: Yes
J1902 = CONN_HDR_10X2: CON 2X10 PLUG SHRD TH 100MIL CTR 366H AU 118L; 3D_Mechanical_Footprint_File: http://fcl.am.freescale.net/ALLEGRO/step/hdr_2x10m_100_th.step; AGILE_PN: 210-80775; CAD_APPROVED: Yes; HEIGHT: 9.3MM; MFG_NAME01: SHENZHEN ATOM TECHNOLOGY CO.,LTD; Package Type: TH; ROHS: Yes
L1901 L2002 L2003 = BEAD_0: IND FER BEAD 120OHM@100MHZ 2A 25% 0603; AGILE_PN: 180-30008; CAD_APPROVED: Yes; FPLIST: IND_0603,0603_CC; HEIGHT: 0.95MM; MFG_NAME01: MURATA; MFG_PN01: BLM18PG121SH1; PART_TYPE: FERRITE; ROHS: Yes; Tolerance: 25%
L1902 = DLW43: IND CHK 90 OHM@100MHZ 330MA 25% 0805; 3D_Mechanical_Footprint_File: http://fcl.am.freescale.net/ALLEGRO/step/ind4_choke_0805_39h.STEP; AGILE_PN: 180-76336; CAD_APPROVED: Yes; HEIGHT: 1MM; MFG_NAME01: MURATA; MFG_PN01: DLW21HN900SQ2L; PART_TYPE: CHOKE; ROHS: Yes; Temp Range: -40°C to +85°C; Tolerance: 25%
R1915 = RES: RES MF 100 OHM 1/16W 5% 0402; AGILE_PN: 470-75591; CAD_APPROVED: Yes; FPLIST: RC0402_25,RC0402_HD,RC0402_X2,0402_CC; HEIGHT: 0.45mm; MFG_NAME01: NIC COMPONENTS CORP; MFG_PN01: NRCL04J101TRF; ROHS: Yes; Tolerance: 5%
U1901 = CP2102: IC USB-TO-UART BRIDGE 3.3V QFN28; 3D_Mechanical_Footprint_File: http://fcl.am.freescale.net/ALLEGRO/step/qfn28_5x5mm_3p3_ep.STEP; AGILE_PN: 312-75932; CAD_APPROVED: Yes; HEIGHT: 1MM; MFG_NAME01: SILICON LABORATORIES; MFG_PN01: CP2102-GM; ROHS: Yes; VOLTAGE: 3.6V
U1902 = SN74LVC2G126DCTR: IC BUF DUAL TS 1.65-5.5V SSOP8; 3D_Mechanical_Footprint_File: http://fcl.am.freescale.net/ALLEGRO/step/ssop8.step; AGILE_PN: 312-80905; CAD_APPROVED: Yes; HEIGHT: 1.30 MM; MFG_NAME01: TEXAS INSTRUMENTS; ROHS: Yes
C2001 C2006 = CAP_NP: CAP CER 0.1UF 25V 10% X5R 0402; AGILE_PN: 150-78633; CAD_APPROVED: Yes; FPLIST: CC0402_25,CC0402_HD,0402_CC; HEIGHT: 0.55MM; MFG_NAME01: YAGEO AMERICA; MFG_PN01: CC0402KRX5R8BB104; Package Size: 0402; ROHS: Yes; Rated Voltage: 25V; TOL: 10%; Temp Range: -55C to +85C; Tolerance: 10%; VOLTAGE: 25V
C2003 = CAP_NP: CAP CER 1.0UF 10V 10% X5R 0402; AGILE_PN: 150-75772; CAD_APPROVED: Yes; FPLIST: CC0402_25,CC0402_HD,0402_CC; HEIGHT: 0.6MM; MFG_NAME01: YAGEO AMERICA; MFG_PN01: CC0402KRX5R6BB105; Package Size: 0402; ROHS: Yes; Rated Voltage: 10V; Temp Range: -55C to +85C; Tolerance: 10%; VOLTAGE: 10V
C2004 = CAP_NP: CAP CER 47uF 10V 20% X5R 0805; AGILE_PN: 150-78979; CAD_APPROVED: Yes; FPLIST: CC0805_OV,CC0805,0805_CC; HEIGHT: 1.45 MM; MFG_NAME01: TDK; MFG_PN01: C2012X5R1A476M125AC; ROHS: Yes; Rated Voltage: 10V; Temp Range: -55C to +85C; Tolerance: 20%; VOLTAGE: 10V
C2005 = CAP_NP: CAP CER 0.01UF 50V 10% X7R 0402; AGILE_PN: 150-30114; CAD_APPROVED: Yes; FPLIST: CC0402_25,CC0402_HD,0402_CC; HEIGHT: 0.55 MM; MFG_NAME01: MURATA; MFG_PN01: GRM155R71H103KA88D; ROHS: Yes; Rated Voltage: 50V; Temp Range: -55C to +125C; Tolerance: 10%; VOLTAGE: 50V
D2001 = ZDIODE: DIODE ZNR -- 0.2W 5.1V AEC-Q101 SOD523; AGILE_PN: 480-77217; CAD_APPROVED: Yes; HEIGHT: 0.7MM; MFG_NAME01: ON SEMICONDUCTOR; ROHS: Yes
D2003 = LED_DUAL_SEP_RG: LED RED GRN DUAL 30/25MA SMT; 3D_Mechanical_Footprint_File: http://fcl.am.freescale.net/ALLEGRO/step/led_dual_3025mm_sm.STEP; AGILE_PN: 370-75097; CAD_APPROVED: Yes; HEIGHT: 1.1MM; MFG_NAME01: KINGBRIGHT; MFG_PN01: APB3025ESGC-F01; ROHS: Yes
J2001 = PHONEJACK-3: CON 1 PWR PLUG RA TH 2.5A 20V -- 441H SN/NI; 3D_Mechanical_Footprint_File: http://fcl.am.freescale.net/ALLEGRO/step/con3_pwr_th.step; AGILE_PN: 210-80780; CAD_APPROVED: Yes; HEIGHT: 11.2MM; MFG_NAME01: SHENZHEN ATOM TECHNOLOGY CO.,LTD; MFG_PN01: DC060024202; Package Type: TH; ROHS: Yes
J2002 = HDR_1X2_TH: HDR 1X2 TH 100MIL SP 461H SN; 3D_Mechanical_Footprint_File: http://fcl.am.freescale.net/ALLEGRO/step/hdr102_100mil.STEP; AGILE_PN: 210-76455; ASSY_OPT: DNP; CAD_APPROVED: Yes; HEIGHT: 11.7MM; MFG_NAME01: MOLEX; MFG_PN01: 22-27-2021; ROHS: Yes
JP2001 = JUMPER1x2: CON 2 JUMPER MALE 2.54MM SP 157H AU; 3D_Mechanical_Footprint_File: http://fcl.am.freescale.net/ALLEGRO/step/100mil_th.STEP; AGILE_PN: 210-30004; ASSY_OPT: DNP; CAD_APPROVED: Yes; HEIGHT: 4MM; MFG_NAME01: PRECI-DIP CONNECTION TECHNOLOGY; MFG_PN01: 999-11-110-10; ROHS: Yes
Q2001 = PNP: TRAN PNP GEN AMP 200MA 40V AEC-Q101 SC75; AGILE_PN: 480-78465; CAD_APPROVED: Yes; HEIGHT: 0.9 MM; MFG_NAME01: ON SEMICONDUCTOR; ROHS: Yes
Q2002 Q2003 = FDMA530PZ: TRAN PMOS PWR 30V 6.8A; 3D_Mechanical_Footprint_File: http://fcl.am.freescale.net/ALLEGRO/step/MLP6_2X2MM_SLUG.STEP; AGILE_PN: 480-77039; CAD_APPROVED: Yes; HEIGHT: 0.8MM; MFG_NAME01: FAIRCHILD; ROHS: Yes
Q2004 = 2SK3018: TRANS MOSFET N-CH 30V .1A SOT-323; AGILE_PN: 480-75317; CAD_APPROVED: Yes; HEIGHT: 0.9MM; MFG_NAME01: ROHM; MFG_PN01: 2SK3018T106; ROHS: Yes
R2001 R2012 = RES: RES MF 3.3K 1/10W 5% 0603; AGILE_PN: 470-75402; CAD_APPROVED: Yes; FPLIST: RC0603_OV,RC0603,0603_CC; HEIGHT: 0.6MM; MFG_NAME01: BOURNS; MFG_PN01: CR0603-JW-332ELF; ROHS: Yes; Tolerance: 5%
R2002 = RES: RES MF 10K 1/16W 5% 0402; AGILE_PN: 470-75557; CAD_APPROVED: Yes; FPLIST: RC0402_25,RC0402_HD,0402_CC; HEIGHT: 0.4 MM; MFG_NAME01: VISHAY INTERTECHNOLOGY; MFG_PN01: CRCW040210K0JNED; ROHS: Yes; TOL: 5%; Tolerance: 5%
R2003 = RES: RES MF 100K 1/16W 5% 0402; AGILE_PN: 470-75597; CAD_APPROVED: Yes; FPLIST: RC0402_25,RC0402_HD,0402_CC; HEIGHT: 0.40 MM; MFG_NAME01: VENKEL COMPANY; MFG_PN01: CR0402-16W-104JT; ROHS: Yes; Temp Range: -55C to +155C; Temp_Range: -55C to +155C; Tolerance: 5%
R2006 = RES: RES MF 2.2K 1/10W 5% 0603; AGILE_PN: 470-75399; CAD_APPROVED: Yes; FPLIST: RC0603_OV,RC0603,0603_CC; HEIGHT: 0.55MM; MFG_NAME01: VENKEL COMPANY; MFG_PN01: CR0603-10W-222JT; ROHS: Yes; Tolerance: 5%
R2007 R2011 = RES: RES MF 100K 1/16W 5% 0402; AGILE_PN: 470-75597; ASSY_OPT: DNP; CAD_APPROVED: Yes; FPLIST: RC0402_25,RC0402_HD,0402_CC; HEIGHT: 0.40 MM; MFG_NAME01: VENKEL COMPANY; MFG_PN01: CR0402-16W-104JT; ROHS: Yes; Temp Range: -55C to +155C; Temp_Range: -55C to +155C; Tolerance: 5%
R2009 = RES: RES MF 100K 1/16W 5% 0402; AGILE_PN: 470-75597; CAD_APPROVED: Yes; FPLIST: RC0402_25,RC0402_HD,0402_CC; HEIGHT: 0.40 MM; MFG_NAME01: VENKEL COMPANY; MFG_PN01: CR0402-16W-104JT; ROHS: Yes; TOL: 5%; Temp Range: -55C to +155C; Temp_Range: -55C to +155C; Tolerance: 5%
R2015 R2016 = RES: RES MF ZERO OHM 1/8W -- 0805; AGILE_PN: 470-75442; ASSY_OPT: DNP; CAD_APPROVED: Yes; FPLIST: RC0805_OV,RC0805,RC0805_OV_3P,0805_CC; HEIGHT: 0.7 MM; MFG_NAME01: YAGEO AMERICA; MFG_PN01: RC0805JR-070RL; ROHS: Yes; Temp Range: –55 °C to +155 °C; Tolerance: 5%
R2128 = RES: RES MF 160K 1/10W 1% AEC-Q200 0402; AGILE_PN: 470-31082; CAD_APPROVED: Yes; FPLIST: RC0402_25,RC0402_HD,0402_CC; HEIGHT: 0.40 MM; MFG_NAME01: KOA SPEER; MFG_PN01: RK73H1ETTP1603F; ROHS: Yes; Temp Range: -55C to +155C; Tolerance: 1%
R2129 = RES: RES MF 200K 1/10W 1% AEC-Q200 0402; AGILE_PN: 470-31093; CAD_APPROVED: Yes; FPLIST: RC0402_25,RC0402_HD,0402_CC; HEIGHT: 0.40 MM; MFG_NAME01: KOA SPEER; MFG_PN01: RK73H1ETTP2003F; ROHS: Yes; Temp Range: -55C to +155C; Temp_Range: -55C to +155C; Tolerance: 1%
SW2001 = SW_DPDT_3: SW DPDT SLD 0.1A 12V L=4 TH; 3D_Mechanical_Footprint_File: http://fcl.am.freescale.net/ALLEGRO/step/sw6_dpdt_11x6mm.STEP; AGILE_PN: 510-77598; CAD_APPROVED: Yes; HEIGHT: 9.5MM; MFG_NAME01: E SWITCH; ROHS: Yes
TVS2002 = DIODE_BIDIR: DIODE BIDIR ESD PROT 3.5pF 5V 1A SOD-962; 3D_Mechanical_Footprint_File: http://fcl.am.freescale.net/ALLEGRO/step/dsn0603-2.STEP; AGILE_PN: 480-79836; CAD_APPROVED: Yes; HEIGHT: 0.32MM; MFG_NAME01: NEXPERIA; MFG_PN01: PESD5V0V1BSF,315; Temp Range: -55°C to +150°C
U2106 = UM1750S-00_5P: IC VREG LDO ADJ 1-5V 350mA 2.5-6V SOT23-5; 3D_Mechanical_Footprint_File: http://fcl.am.freescale.net/ALLEGRO/step/sot23-5_a.STEP; AGILE_PN: 315-80554; CAD_APPROVED: Yes; HEIGHT: 1.25MM; MFG_NAME01: UNION SEMICONDUCTOR, INC; ROHS: Yes; VOLTAGE: 2.5-6V

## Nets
DVDD_1V8: C2159.1 C2160.1 R2128.1 TP2131.1(TP) U2106.5(OUT) ; also on sheet 5
GND: C1001.2 C1002.2 C1003.2 C1004.2 C1005.2 C1006.2 C1007.2 C1008.2 C1009.2 C1010.2 C1011.2 C1012.2 C1013.2 C1014.2 C1015.2 C1016.2 C1017.2 C1501.2 C1502.2 C1503.2 C1504.2 C1505.2 C1506.2 C1507.2 C1508.2 C1601.2 C1602.2 C1603.2 C1604.2 C1605.2 C1606.2 C1607.2 C1608.2 C1901.2 C1902.2 C1903.2 C1904.2 C1905.2 C2001.2 C2002.2 C2003.2 C2004.2 C2006.2 C2009.2 C2011.2 C2157.2 C2158.2 C2159.2 C2160.2 D1901.3(ANODE) D2001.A(ANODE) D2003.4(CATHODE2) J1001.2(D2GND) J1001.5(D1GND) J1001.8(D0GND) J1001.11(CKGND) J1001.17(DDCGND) J1901.5(GND1) J1902.4 J1902.6 J1902.8 J1902.10 J1902.12 J1902.14 J1902.16 J1902.18 J1902.20 J2001.2 J2001.3 J2002.2 L2003.1 Q2003.3(G) Q2004.1(SOURCE) R1013.2 R1015.2 R1018.2 R1025.2 R1515.2 R1517.2 R1518.2 R1519.2 R1522.2 R1523.2 R1524.2 R1528.2 R1530.2 R1531.2 R1532.2 R1534.2 R1613.2 R1615.2 R1616.2 R1617.2 R1620.2 R1621.2 R1622.2 R1626.2 R1628.2 R1629.2 R1630.2 R1632.2 R1904.1 R1916.2 R1917.2 R1919.2 R2009.2 R2011.2 R2106.2 R2129.2 SW2001.3(NO1) SW2001.6(NO2) TP1906.1(TP) TP2003.1(TP) TVS1001.1(C1) TVS1002.1(C1) TVS1003.1(C1) TVS1004.1(C1) TVS1005.1(C1) TVS1901.1(C1) U1001.37(SD3) U1001.38(MCLK) U1001.39(SD2) U1001.40(SD1) U1001.41(SD0) U1001.43(CGND) U1001.44(WS) U1001.45(SCK) U1001.55(RSVDL) U1001.57(IOGND) U1001.63(AGND) U1001.70(VDDQ) U1001.73(EPAD) U1002.2(GND) U1003.2(GND) U1004.1(GND) U1501.1(GND) U1501.33(PADDLE) U1502.2(GND) U1601.1(GND) U1601.33(PADDLE) U1602.2(GND) U1901.3(GND) U1901.29(EPAD) U1902.4(GND) U2106.2(GND) ; also on sheet 3 4 5 6 7 8 17 18
GND_CHASSIS: J1501.P8A(GND_A) J1501.P8B(GND_B) J1501.SH1 J1501.SH2 J1501.SH3 ; also on sheet 17
VBUS_CP210x: C1901.1 C1905.1 L1901.2 U1901.7(REGIN) U1901.8(VBUS)
VBUS_DGB: J1901.1(VBUS) L1901.1 R2015.1 R2016.1 TVS1901.2(C2)
VDDCO_1_1V8: C1503.1 C1504.1 U1501.2(VDD_1.2)
VDDCO_2_1V8: C1603.1 C1604.1 U1601.2(VDD_1.2)
DC_5V_IN: C2001.1 J2001.1 J2002.1 Q2003.1(D1) Q2003.2(D2) Q2003.5(D5) Q2003.6(D6) Q2003.7(D7) R2004.1 R2013.1 R2014.1 R2015.2 R2016.2 TP2001.1(TP)
DCDC_3V3: C1904.1 D1906.A J1902.2 R1026.1 R1905.1 R1910.1 R1912.1 R1913.1 R1914.1 R1915.1 TP1905.1(TP) U1902.8(VCC) ; also on sheet 3 4 8 17 18
DCDC_5V: C1012.1 C1013.1 C2009.1 C2011.1 D1001.A L2002.2 R1019.1 R1020.1 R1024.1 ; also on sheet 7 17 18
DDC_SCL: J1001.15(SCL) R1020.2 TVS1003.2(C2) U1001.49(DSCL)
DDC_SDA: J1001.16(SDA) R1019.2 TVS1002.2(C2) U1001.48(DSDA)
ECSPI4_MISO: R1636.1 ; also on sheet 3 8 18
ECSPI4_MOSI: R1635.1 ; also on sheet 3 8 18
ECSPI4_SCLK: R1634.1 ; also on sheet 3 8 18
ECSPI4_SS0: R1633.1 ; also on sheet 3 8 18
ENET1_B-CAST-OFF: R1533.1 TP1501.1(TP) U1501.19(REF_CLK/B-CAST_OFF)
ENET1_CONFIG0: R1522.1 R1525.1 U1501.28(CONFIG0)
ENET1_CONFIG1: R1523.1 R1526.1 U1501.29(CONFIG1)
ENET1_CRS_DV: R1524.1 R1527.1 U1501.18(CRS_DV/CONFIG2) ; also on sheet 3
ENET1_LED0/NWAYEN: R1505.1 R1530.1 U1501.30(LED0/NWAYEN)
ENET1_LED1/SPEED: R1507.1 R1531.1 U1501.31(LED1/SPEED)
ENET1_nINT: R1508.2 R1534.1 U1501.21(INTRP/~{NAND_TREE}) ; also on sheet 3
ENET1_nRST: C1508.1 C1608.1 R1509.2 R1607.2 U1501.32(~{RST}) U1601.32(~{RST}) ; also on sheet 3
ENET1_PHYAD0: R1516.1 R1519.1 U1501.13(PHYAD0)
ENET1_PHYAD1: R1517.1 R1520.1 U1501.14(PHYAD1)
ENET1_RXD0: R1532.1 U1501.16(RXD0/DUPLEX) ; also on sheet 3
ENET1_RXD1: R1518.1 R1521.1 U1501.15(RXD1/PHYAD2) ; also on sheet 3
ENET1_RXER: R1528.1 R1529.1 U1501.20(RXER/ISO) ; also on sheet 3
ENET1_TX_CLK: TP1502.1(Pin1) U1501.9(XI) ; also on sheet 3
ENET1_TXD0: TP1503.1(Pin1) U1501.24(TXD0) ; also on sheet 3
ENET1_TXD1: U1501.25(TXD1) ; also on sheet 3
ENET1_TXEN: U1501.23(TXEN) ; also on sheet 3
ENET2_B-CAST-OFF: R1631.1 TP1601.1(TP) U1601.19(REF_CLK/B-CAST_OFF)
ENET2_CONFIG0: R1620.1 R1623.1 U1601.28(CONFIG0)
ENET2_CONFIG1: R1621.1 R1624.1 U1601.29(CONFIG1)
ENET2_CRS_DV: R1622.1 R1625.1 U1601.18(CRS_DV/CONFIG2) ; also on sheet 3
ENET2_ISO: R1626.1 R1627.1 R1633.2 U1601.20(RXER/ISO)
ENET2_LED0/NWAYEN: R1603.1 R1628.1 U1601.30(LED0/NWAYEN)
ENET2_LED1/SPEED: R1605.1 R1629.1 U1601.31(LED1/SPEED)
ENET2_nINT: R1606.2 R1632.1 U1601.21(INTRP/~{NAND_TREE}) ; also on sheet 3
ENET2_PHYAD0: R1614.1 R1617.1 U1601.13(PHYAD0)
ENET2_PHYAD1: R1615.1 R1618.1 U1601.14(PHYAD1)
ENET2_RXD0: R1630.1 U1601.16(RXD0/DUPLEX) ; also on sheet 3
ENET2_RXD1: R1616.1 R1619.1 U1601.15(RXD1/PHYAD2) ; also on sheet 3
ENET2_TXD0: TP1602.1(Pin1) U1601.24(TXD0) ; also on sheet 3
ENET_MDC: R1504.2 U1501.12(MDC) U1601.12(MDC) ; also on sheet 3
ENET_MDIO: R1501.2 U1501.11(MDIO) U1601.11(MDIO) ; also on sheet 3
ETH1_RXM: J1501.P6A U1501.4(RXM) U1502.3(I/O3)
ETH1_RXP: J1501.P3A U1501.5(RXP) U1502.1(I/O1)
ETH1_TXM: J1501.P2A U1501.6(TXM) U1502.4(I/O4)
ETH1_TXP: J1501.P1A U1501.7(TXP) U1502.6(I/O6)
ETH2_RXM: J1501.P6B U1601.4(RXM) U1602.3(I/O3)
ETH2_RXP: J1501.P3B U1601.5(RXP) U1602.1(I/O1)
ETH2_TXM: J1501.P2B U1601.6(TXM) U1602.4(I/O4)
ETH2_TXP: J1501.P1B U1601.7(TXP) U1602.6(I/O6)
HDMI_5V: D1001.C J1001.18(+5V) R1024.2 TVS1001.2(C2)
HDMI_CEC_A: J1001.13(CEC) R1021.2 TVS1004.2(C2) U1001.71(CEC_A)
HDMI_CEC_D: R1004.2 U1001.50(CEC_D)
HDMI_CLKN_CN: J1001.12(CK-) L1003.2 R1010.2 U1003.1(I/O1)
HDMI_CLKP_CN: J1001.10(CK+) L1003.3 R1014.2 U1003.3(I/O3)
HDMI_DATAN0_CN: J1001.9(D0-) L1001.2 R1002.2 U1003.6(I/O6)
HDMI_DATAN1_CN: J1001.6(D1-) L1004.2 R1009.2 U1002.6(I/O6)
HDMI_DATAN2_CN: J1001.3(D2-) L1002.2 R1003.2 U1002.1(I/O1)
HDMI_DATAP0_CN: J1001.7(D0+) L1001.3 R1005.2 U1003.4(I/O4)
HDMI_DATAP1_CN: J1001.4(D1+) L1004.3 R1011.2 U1002.4(I/O4)
HDMI_DATAP2_CN: J1001.1(D2+) L1002.3 R1007.2 U1002.3(I/O3)
HDMI_GND_CHASSIS: J1001.G1(GND1) J1001.G2(GND2) J1001.G3(GND3) J1001.G4(GND4) R2106.1
HDMI_HPD: J1001.19(HPD) R1025.1 TVS1005.2(C2) U1001.54(HPD)
HDMI_INT: R1006.2 U1001.52(INT) ; also on sheet 3
HDMI_nRST: R1016.2 U1001.51(~{RESET}) ; also on sheet 3
I2C2_SCL: R1008.1 ; also on sheet 3 4 5 8 18
I2C2_SDA: R1001.1 ; also on sheet 3 4 5 8 18
JTAG_DACK: J1902.19 R1919.1
JTAG_DE: J1902.17 R1910.2
JTAG_nSRST: D1905.C J1902.15 R1911.2
JTAG_nTRST: J1902.3 R1914.2 ; also on sheet 3 5
JTAG_RTCK: J1902.11 R1917.1
JTAG_TCK: J1902.9 R1916.1 ; also on sheet 3 5
JTAG_TDI: J1902.5 R1913.2 ; also on sheet 3 5
JTAG_TDO: J1902.13 ; also on sheet 3 5
JTAG_TMS: J1902.7 R1912.2 ; also on sheet 3 5
JTAG_VREF: J1902.1 R1915.2
LCD_DATA0: U1001.32(D0) ; also on sheet 3 8
LCD_DATA1: U1001.31(D1) ; also on sheet 3 8
LCD_DATA2: U1001.30(D2) ; also on sheet 3 8
LCD_DATA3: U1001.29(D3) ; also on sheet 3 8
LCD_DATA4: U1001.28(D4) ; also on sheet 3 8
LCD_DATA5: U1001.27(D5) ; also on sheet 3 8
LCD_DATA6: U1001.25(D6) ; also on sheet 3 8
LCD_DATA7: U1001.24(D7) ; also on sheet 3 8
LCD_DATA8: U1001.23(D8) ; also on sheet 3 8
LCD_DATA9: U1001.20(D9) ; also on sheet 3 8
LCD_DATA10: U1001.19(D10) ; also on sheet 3 8
LCD_DATA11: U1001.18(D11) ; also on sheet 3 8
LCD_DATA12: U1001.17(D12) ; also on sheet 3 8
LCD_DATA13: U1001.16(D13) ; also on sheet 3 8
LCD_DATA14: U1001.15(D14) ; also on sheet 3 8
LCD_DATA15: U1001.14(D15) ; also on sheet 3 8
LCD_DATA16: U1001.13(D16) ; also on sheet 3 8
LCD_DATA17: U1001.11(D17) ; also on sheet 3 8
LCD_DATA18: U1001.10(D18) ; also on sheet 3 8
LCD_DATA19: U1001.9(D19) ; also on sheet 3 8
LCD_DATA20: U1001.8(D20) ; also on sheet 3 8
LCD_DATA21: U1001.7(D21) ; also on sheet 3 8
LCD_DATA22: U1001.6(D22) ; also on sheet 3 8
LCD_DATA23: U1001.4(D23) ; also on sheet 3 8
LCD_DE: U1001.33(DE) ; also on sheet 3 8
LCD_HSYNC: U1001.34(HSYNC) ; also on sheet 3 8
LCD_PCLK: R1017.1 ; also on sheet 3 8
LCD_VSYNC: U1001.35(VSYNC) ; also on sheet 3 8
nSLEEP: R1909.1 U1901.11(~{SUSPEND})
POR_B: D1905.A ; also on sheet 3 18
SLEEP: R1908.1 U1901.12(SUSPEND)
SPDIF_TX: R1023.1 ; also on sheet 3
TMDS_TX0_N: L1001.1 R1002.1 U1001.61(TX0-)
TMDS_TX0_P: L1001.4 R1005.1 U1001.62(TX0+)
TMDS_TX1_N: L1004.1 R1009.1 U1001.64(TX1-)
TMDS_TX1_P: L1004.4 R1011.1 U1001.65(TX1+)
TMDS_TX2_N: L1002.1 R1003.1 U1001.67(TX2-)
TMDS_TX2_P: L1002.4 R1007.1 U1001.68(TX2+)
TMDS_TXC_N: L1003.1 R1010.1 U1001.58(TXC-)
TMDS_TXC_P: L1003.4 R1014.1 U1001.59(TXC+)
UART1_RXD: R1905.2 TP1904.1(TP) U1902.6(1Y) ; also on sheet 3
UART1_TXD: TP1903.1(TP) U1902.5(2A) ; also on sheet 3
USB_DBG_DM: L1902.2 R1901.2 U1901.5(D-)
USB_DBG_DM_CN: D1901.2(CATHODE2) J1901.2(D-) L1902.1 R1901.1
USB_DBG_DP: L1902.3 R1903.2 U1901.4(D+)
USB_DBG_DP_CN: D1901.1(CATHODE1) J1901.3(D+) L1902.4 R1903.1
USB_OTG1_PWR: C2006.1 R2010.2 ; also on sheet 3 8 17 18
USB_RXD: R1907.2 U1901.25(RXD) U1902.3(2Y)
USB_TXD: R1906.2 U1901.26(TXD) U1902.2(1A)
VENET_3V3: C1505.1 C1605.1 C2157.1 C2158.1 J1501.9A(D1A) J1501.9B(D1B) J1501.11A(D3A) J1501.11B(D3B) L1501.1 L1601.1 R1501.1 R1504.1 R1508.1 R1509.1 R1516.2 R1520.2 R1521.2 R1525.2 R1526.2 R1527.2 R1529.2 R1533.2 R1606.1 R1607.1 R1614.2 R1618.2 R1619.2 R1623.2 R1624.2 R1625.2 R1627.2 R1631.2 U1501.17(VDDIO) U1601.17(VDDIO) U2106.1(IN) U2106.3(~{SHDN}) ; also on sheet 3 4 5 6 7 18
VHDMI_3V3: C1003.1 C1004.1 C1005.1 C1014.1 C1015.1 D1002.A R1004.1 R1006.1 R1012.2 R1016.1 R1022.1 R1026.2 U1001.3(IOVCC18_1) U1001.21(IOVCC18_2) U1001.46(IOVCC18_3) U1004.3(VIN)
VLDO_1V2: C1001.1 C1002.1 C1006.1 C1007.1 C1008.1 C1009.1 C1010.1 C1011.1 C1016.1 C1017.1 TP1001.1(TP) U1001.5(CVCC12_1) U1001.12(CVCC12_2) U1001.26(CVCC12_3) U1001.42(CVCC12_4) U1001.47(CVCC12_5) U1001.53(CVCC12_6) U1001.60(AVCC12_1) U1001.66(AVCC12_2) U1004.2(VOUT)
VSYS: C2002.1 C2003.1 C2004.1 JP2001.2 L2002.1 Q2002.1(D1) Q2002.2(D2) Q2002.5(D5) Q2002.6(D6) Q2002.7(D7) R2005.1 R2007.1 TP2002.1(TP) TVS2002.2(C2) ; also on sheet 3 4 5 8
VUSB_UART_3V3: C1902.1 C1903.1 D1903.1(ANODE1) D1903.3(ANODE2) U1901.6(VDD)
WALL_OV_BASE: Q2001.1(B) R2002.2
WALL_OV_CTL: D2001.C(CATHODE) R2001.2 R2002.1
WALL_OVP_LED: D2002.A Q2001.3(C) R2008.1
N95315917: C1501.1 C1502.1 L1501.2 U1501.3(VDDA_3.3)
N95316217: R1515.1 U1501.10(REXT)
N95316788: C1506.1 J1501.P5A
N95316794: C1507.1 J1501.P4A
N97026671: R1015.1 U1001.56(EXT_SWING)
N97026935: R1008.2 U1001.1(CSCL)
N97026974: R1001.2 U1001.2(CSDA)
N97027063: R1012.1 R1013.1 U1001.72(CI2CA)
N97149824: R1022.2 R1023.2 U1001.36(SPDIF)
N97157415: R1018.1 U1001.69(IO_SEL)
N97190616: C2005.2 D2002.C Q2002.3(G) R2003.2 R2006.1
N97190709: C2005.1 JP2001.1 Q2001.2(E) Q2002.4(S1) Q2002.8(S2) Q2003.4(S1) Q2003.8(S2) R2001.1 R2003.1 R2013.2 R2014.2
N97193542: D2003.3(ANODE2) R2005.2
N97194205: D2003.2(CATHODE1) Q2004.3(DRAIN)
N97195087: D2003.1(ANODE1) R2004.2
N97195984: Q2004.2(GATE) R2008.2 R2009.1
N97197821: R2007.2 R2010.1 R2011.1
N97206924: C1601.1 C1602.1 L1601.2 U1601.3(VDDA_3.3)
N97207164: R1613.1 U1601.10(REXT)
N97207545: R1636.2 U1601.9(XI)
N97327737: TP1901.1(TP) U1901.9(~{RST})
N97332896: R1908.2 R1909.2 U1902.1(1OE) U1902.7(2OE)
N97333780: R1904.2 U1901.14(NC3)
N97334203: TP1902.1(TP) U1901.10(NC1)
N97656955: R1017.2 U1001.22(IDCK)
N97662147: D1002.C R1021.1
N98059204: D1906.C R1911.1
N98377066: R2012.2 SW2001.5(COMMON2)
N98377098: R2006.2 R2012.1
N98661532: R1634.2 U1601.25(TXD1)
N98661566: R1635.2 U1601.23(TXEN)
N98803637: D1903.4(CATHODE2) R1907.1
N98803640: D1903.2(CATHODE1) R1906.1
N98827737: J1501.12A(D4A) R1507.2
N98827800: J1501.10A(D2A) R1505.2
N98829436: J1501.12B(D4B) R1605.2
N98829451: J1501.10B(D2B) R1603.2
N98829499: C1607.1 J1501.P4B
N98829505: C1606.1 J1501.P5B
N99945506: J1901.S1(SHLD1) J1901.S2(SHLD2) J1901.S3(SHLD3) J1901.S4(SHLD4) J1901.S5(SHLD5) J1901.S6(SHLD6) L2003.2
N101132105: R2128.2 R2129.1 U2106.4(FB)

Not connected (* = marked no-connect by the designer): J1001 14(Utility)*; J1501 P7A(NC_A)* P7B(NC_B)*; J1901 4(ID)*; SW2001 1(NC1)* 2(COMMON1)* 4(NC2)*; TVS2002 1(C1); U1002 5(VCC); U1003 5(VCC); U1501 8(XO) 22(NC1) 26(NC2) 27(NC3); U1502 5(VCC); U1601 8(XO) 22(NC1) 26(NC2) 27(NC3); U1602 5(VCC); U1901 1(DCD) 2(RI) 13(NC2) 15(NC4) 16(NC5) 17(NC6) 18(NC7) 19(NC8) 20(NC9) 21(NC10) 22(NC11) 23(CTS) 24(RTS) 27(DSR) 28(DTR)

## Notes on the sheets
sheet 12
- HDMI Transmitter
- EMI/ESD
- #Res Overlap with EMI Choke
- Standby: 150 uW
- HDMI TYPEA
- 1.2V PWR
- # 1.2V/100mA Iq = 4μA
- Internal Function
- CI2CA = LOW
- CI2CA = HIGH
- Transmitter Programming Interface (TPI) device address
- 0x72
- 0x76
- CEC Programming Interface (CPI) device address
- 0xC0
- 0xC4
- SiI9020-compatible internal registers: first device address
- 0x72
- 0x76
- SiI9020-compatible internal registers: second device address
- 0x7A
- 0x7E
sheet 13
- 100M ETHERNET RMII PHY x1
- PHY PWR
- Software power-down mode:
  VDDA_3.3:  1.36mA
  VDDIO:     0.45mA
- # VDDIO: 3.3V/2.5V/1.8V
- Ipu/O
- Ipd/O
- Ipd/O
- Ipu/O
- Ipd/O
- Ipd/O
- Ipd/O
- I
- I
- I
- Ipu/O
- Ipu/O
- Ipu/Opu
- Ipd/O
- Ipd/O
- Ipd/O
- RMII CFG
- # CFG
- Description
- # CFG
- Description
- PHY ADDR
- DUPLEX mode
- PHYAD[2:0]
- Ipu/O
- 00-XXX (00001 DEFAULT)
- DUPLEX
- Pull-up  (defaule) = Half Duplex
  Pull-down = Full Duplex
- Ipd/O
- Ipd/O
- IF MODE
- 001 RMII
  101 RMII Back-to-Back
  xxx Reserved-not used
- Nway Auto-Negotiation
- CONFIG[2:0]
- NWAYEN
- Pull-up  (defaule) = Enable
  Pull-down = Disable
- ESD PROTECTION
- Ipd/O
- Ipd/O
- Ipd/O
- ISOLATE mode
- Broadcast Off - for PHY Address 0
- # 2rd LEVEL ESD
- Ipd/O
- ISO
- Pull-up =  Enable
  Pull-down (defaule) = Disable
- B_CAST_OFF
- Pull-up = PHY Address 0 set as unique PHY addr
  Pull-down (default) = PHY Address 0 set as broadcast PHY addr
- Ipu/O
- Ipu/O
- Ipu/O
- Ipd/O
- SPEED mode
- NAND Tree Mode
- Ipu/Opu
- SPEED
- Pull-up  (defaule) =  100Mbps
  Pull-down = 10Mbps
- NAND_TREE#
- Pull-up  (defaule) = Disable
  Pull-down =  Enable
sheet 14
- 100M ETHERNET RMII PHY x2
- # VDDIO: 3.3V/2.5V/1.8V
- Ipu/O
- Ipd/O
- Ipd/O
- Ipd/O
- Ipu/O
- Ipd/O
- Ipd/O
- I
- I
- I
- Ipu/O
- Ipu/O
- Ipd/O
- Ipu/Opu
- Ipd/O
- Ipd/O
- MUX with LCD SPI IF
- RMII CFG
- # CFG
- Description
- # CFG
- Description
- PHY ADDR
- DUPLEX mode
- PHYAD[2:0]
- Ipu/O
- 00-XXX (00001 DEFAULT)
- DUPLEX
- Pull-up  (defaule) = Half Duplex
  Pull-down = Full Duplex
- Ipd/O
- Ipd/O
- IF MODE
- 001 RMII
  101 RMII Back-to-Back
  xxx Reserved-not used
- Nway Auto-Negotiation
- ESD PROTECTION
- CONFIG[2:0]
- NWAYEN
- Pull-up  (defaule) = Enable
  Pull-down = Disable
- Ipd/O
- Ipd/O
- # 2rd LEVEL ESD
- Ipd/O
- ISOLATE mode
- Broadcast Off - for PHY Address 0
- Ipd/O
- ISO
- Pull-up =  Enable
  Pull-down (defaule) = Disable
- B_CAST_OFF
- Pull-up = PHY Address 0 set as unique PHY addr
  Pull-down (default) = PHY Address 0 set as broadcast PHY addr
- Ipu/O
- Ipu/O
- Ipu/O
- Ipd/O
- Ipu/Opu
- SPEED mode
- NAND Tree Mode
- SPEED
- Pull-up  (defaule) =  100Mbps
  Pull-down = 10Mbps
- NAND_TREE#
- Pull-up  (defaule) = Disable
  Pull-down =  Enable
sheet 15
- SYS PWR
- SYS_3V7 POK LED(GRN)
- Over-Voltage LED(RED)
- # RSV for ADC TEST
- 1.8V PWR
- Vfb=1V
- # 1.8V: R1/R2 = 0.64/0.8 : 160K/200K
sheet 16
- UART-USB DBG / JTAG
- USB-UART Bridge
- # Level-Shifter to insure no IO backfeed
- JTAG
- JTAG_PWR
